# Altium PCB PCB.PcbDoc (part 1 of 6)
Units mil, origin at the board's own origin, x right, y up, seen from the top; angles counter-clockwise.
Board outline 7100 x 7000 mil, 4 copper layers (Top Layer, GND, VCC, Bottom Layer), stack 61.2 mil thick; 759 components, 507 nets, 2200 pads, 452 vias.
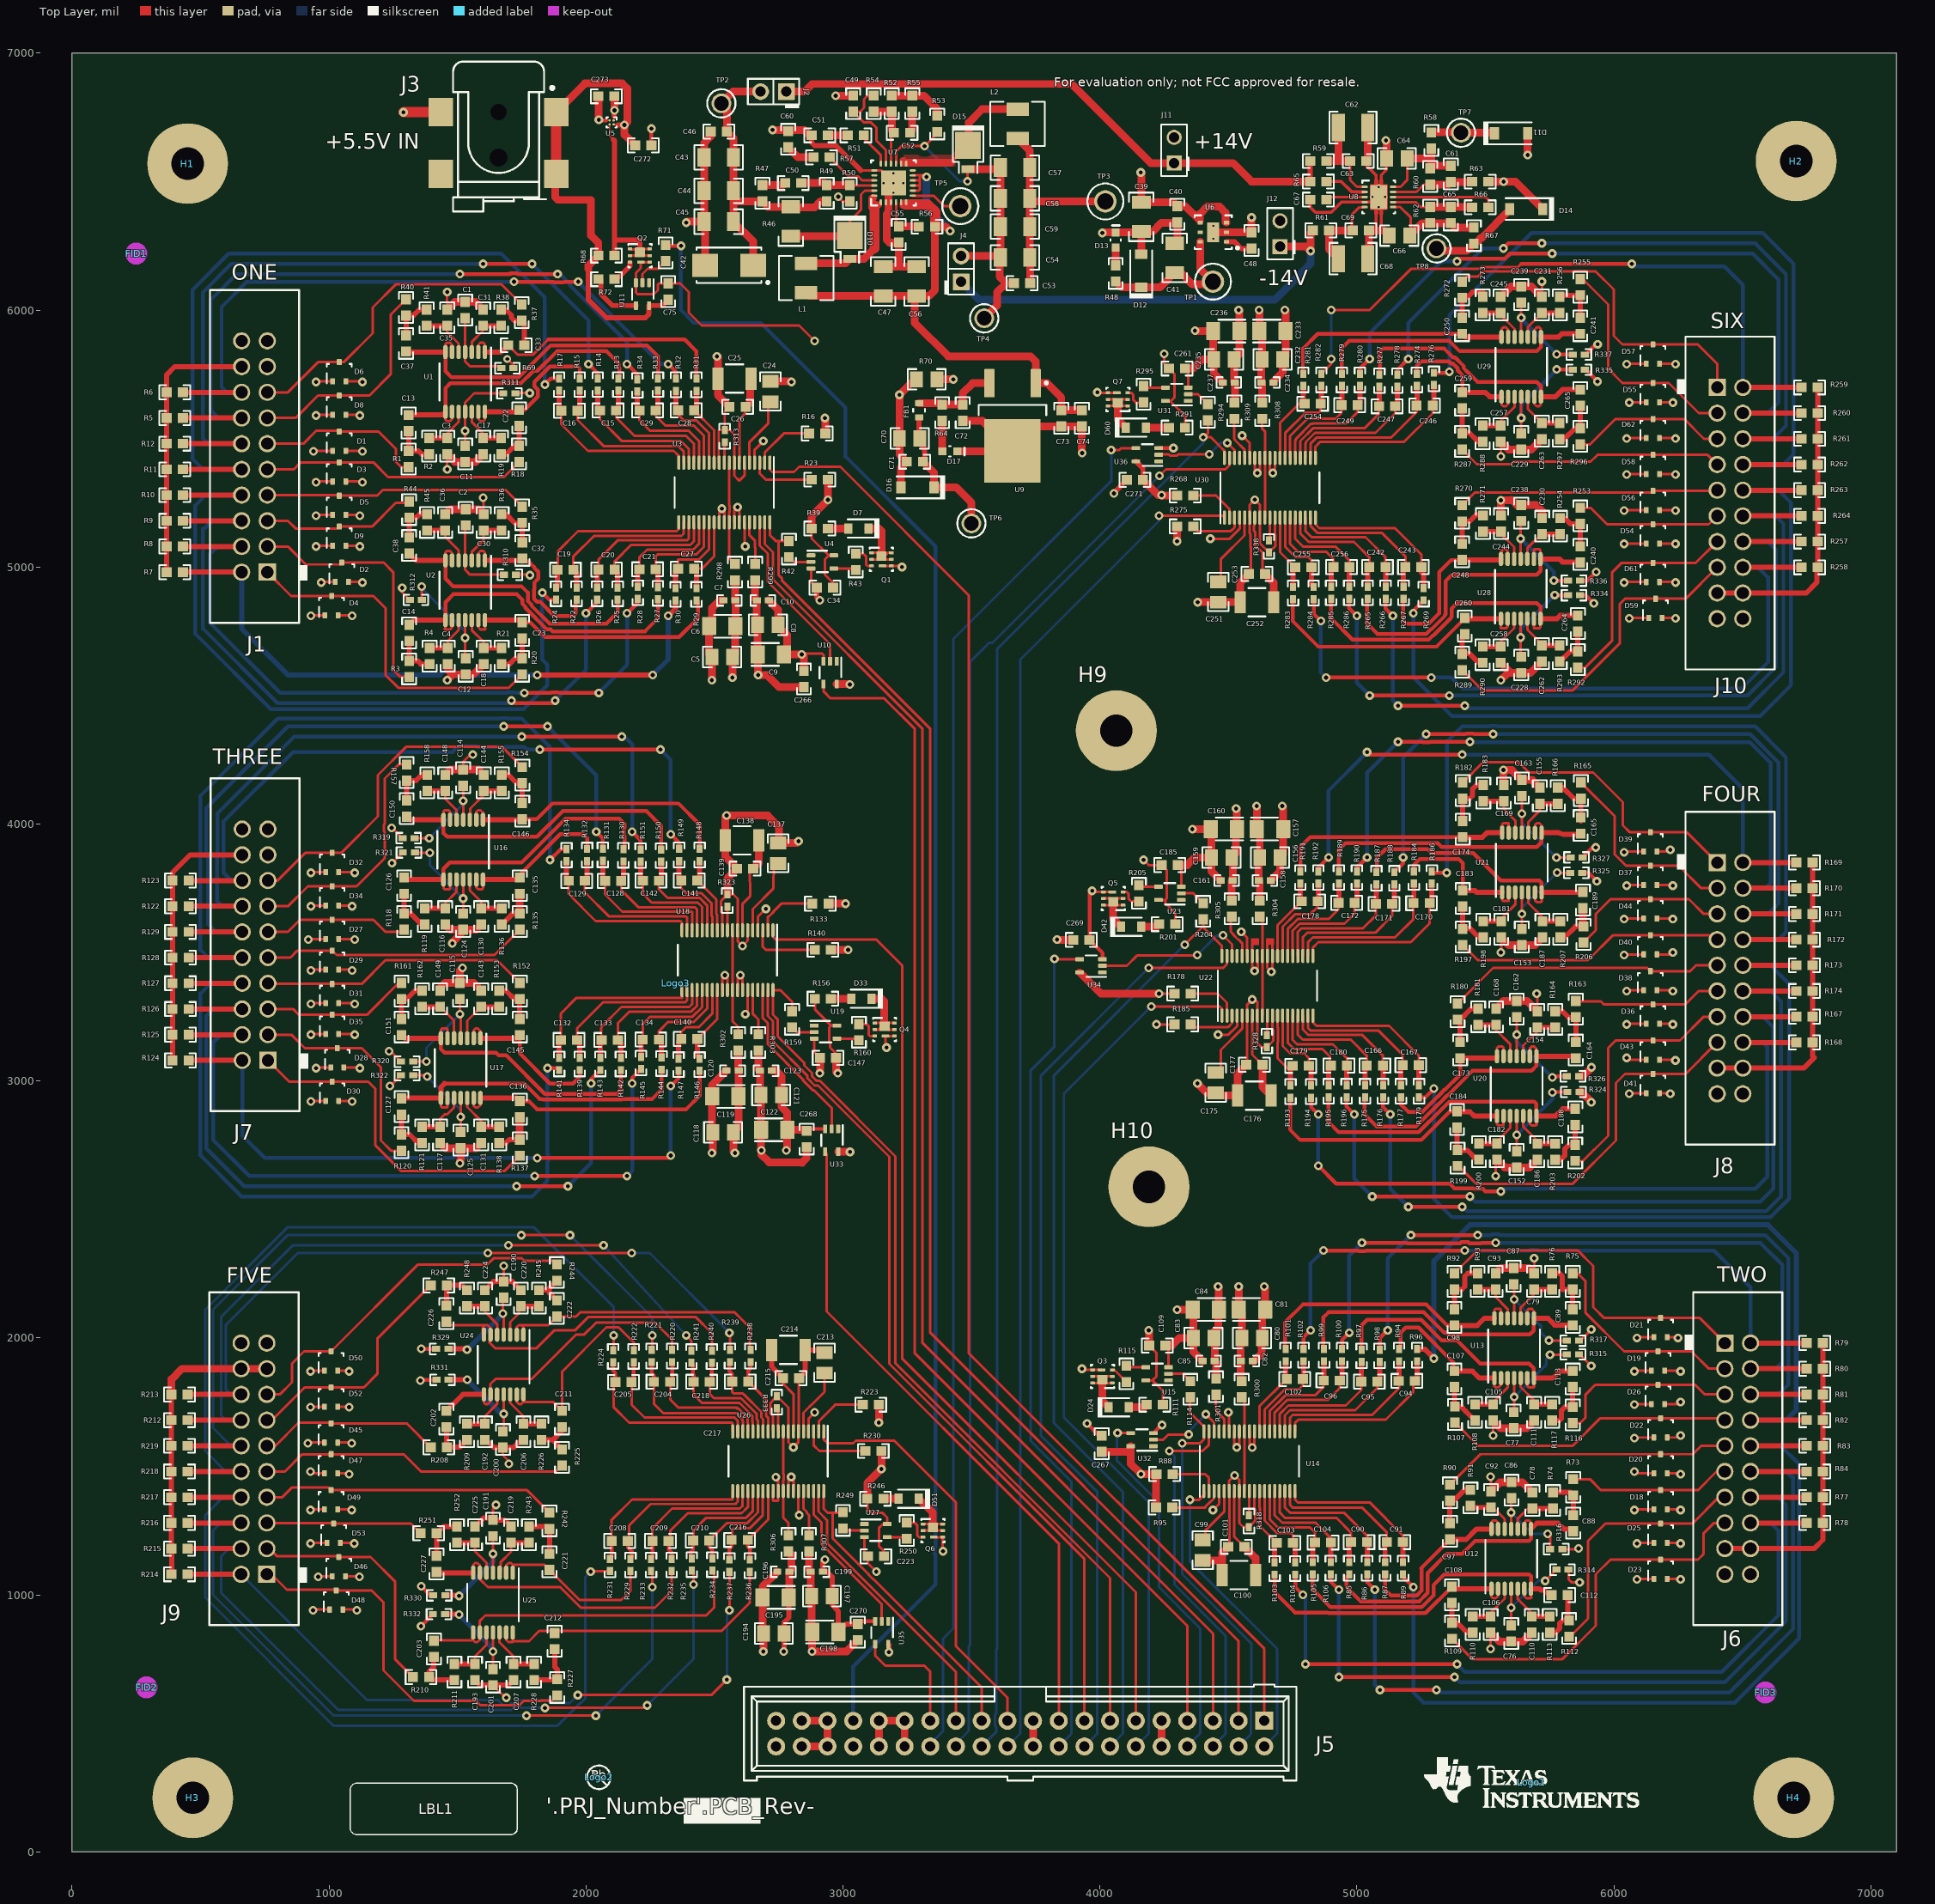
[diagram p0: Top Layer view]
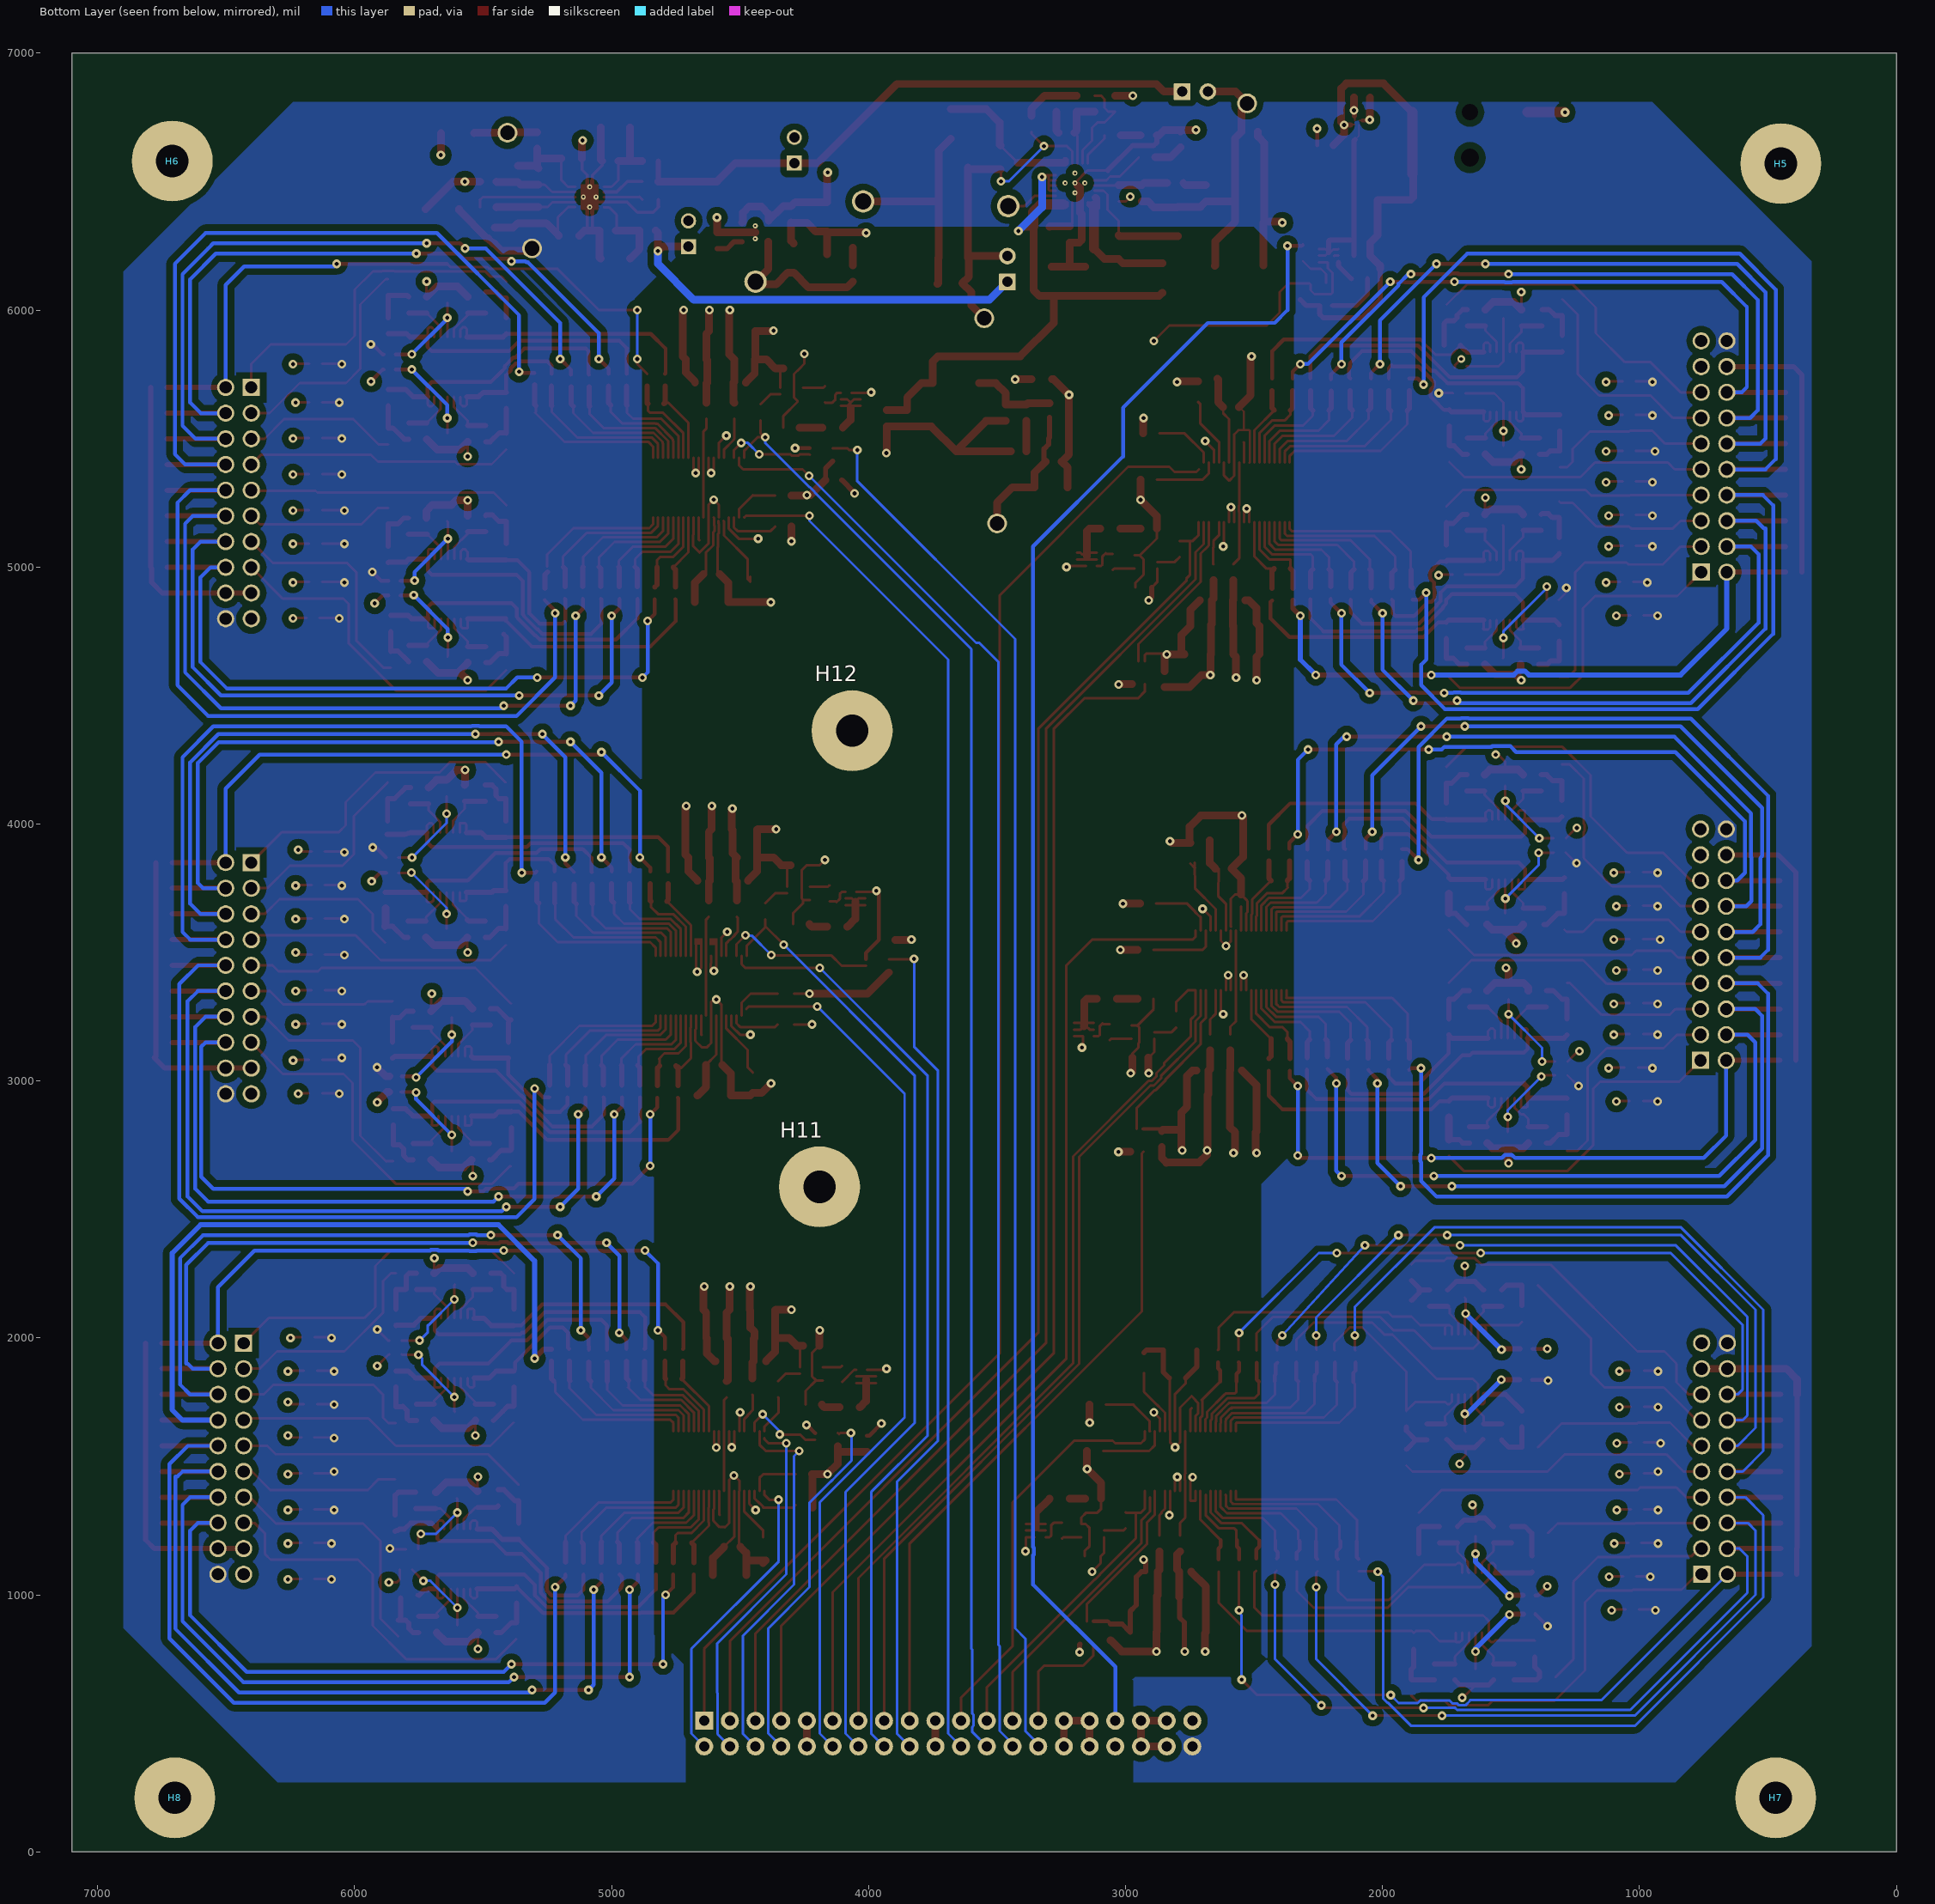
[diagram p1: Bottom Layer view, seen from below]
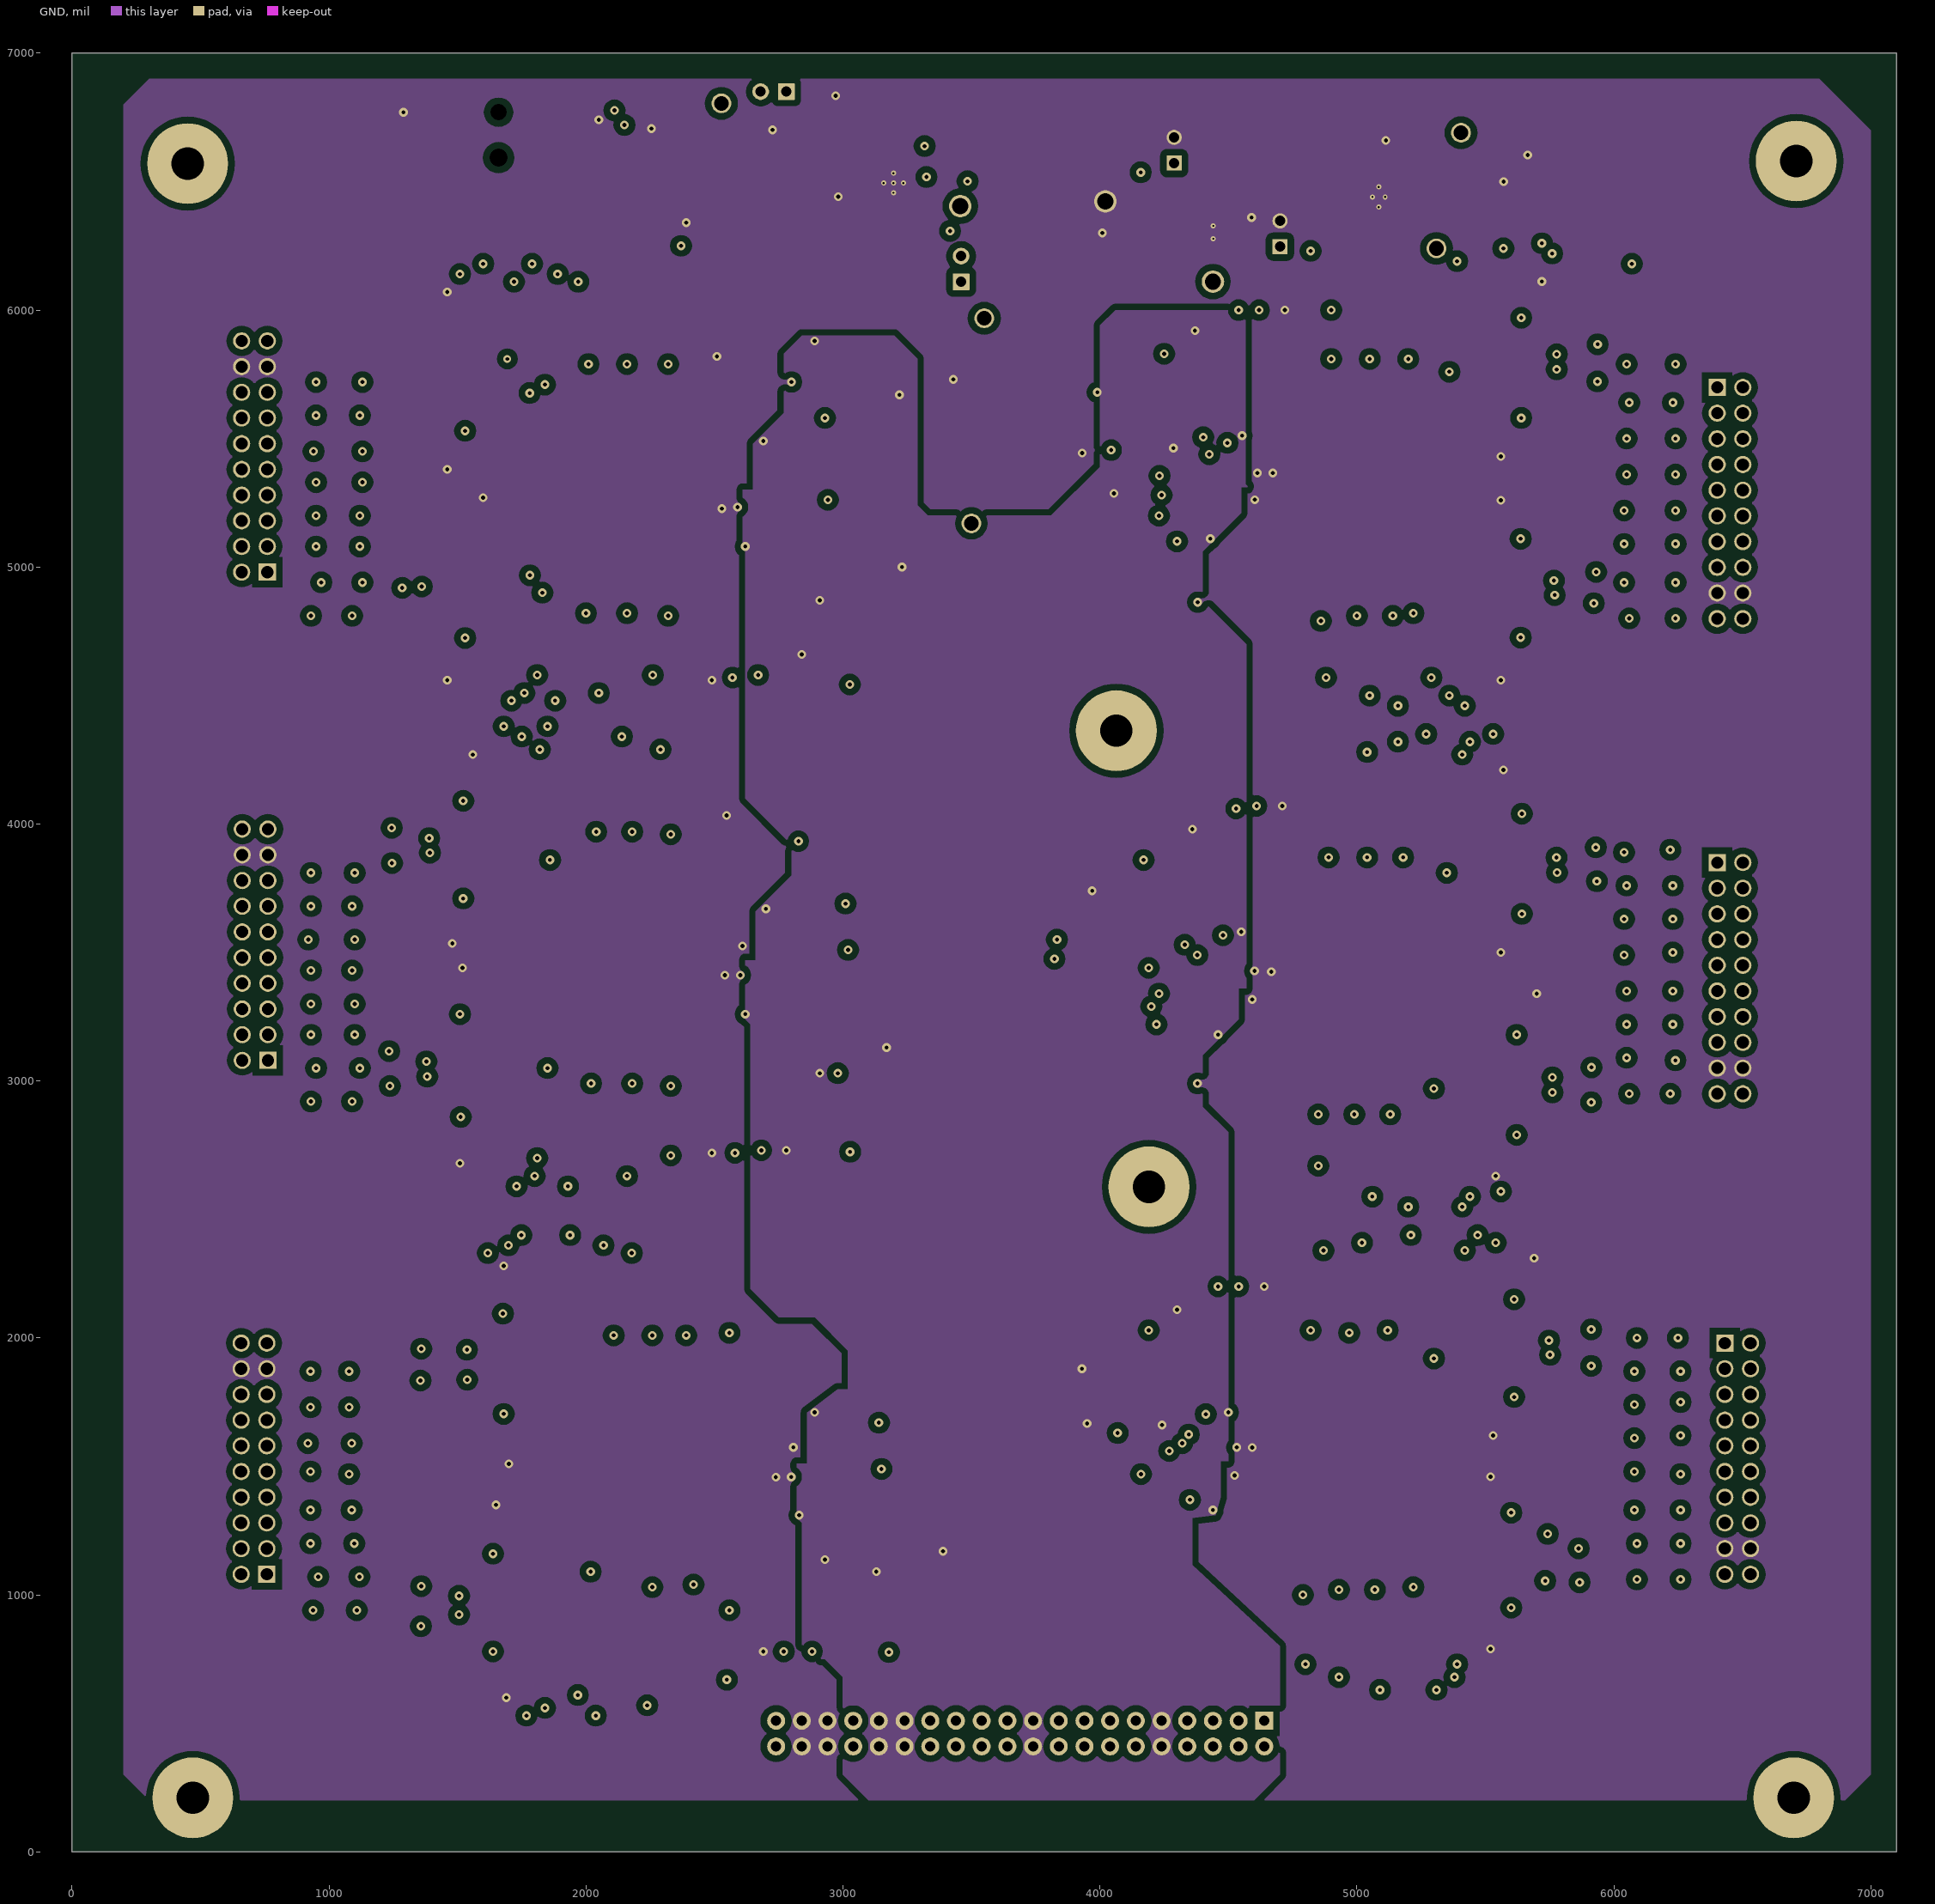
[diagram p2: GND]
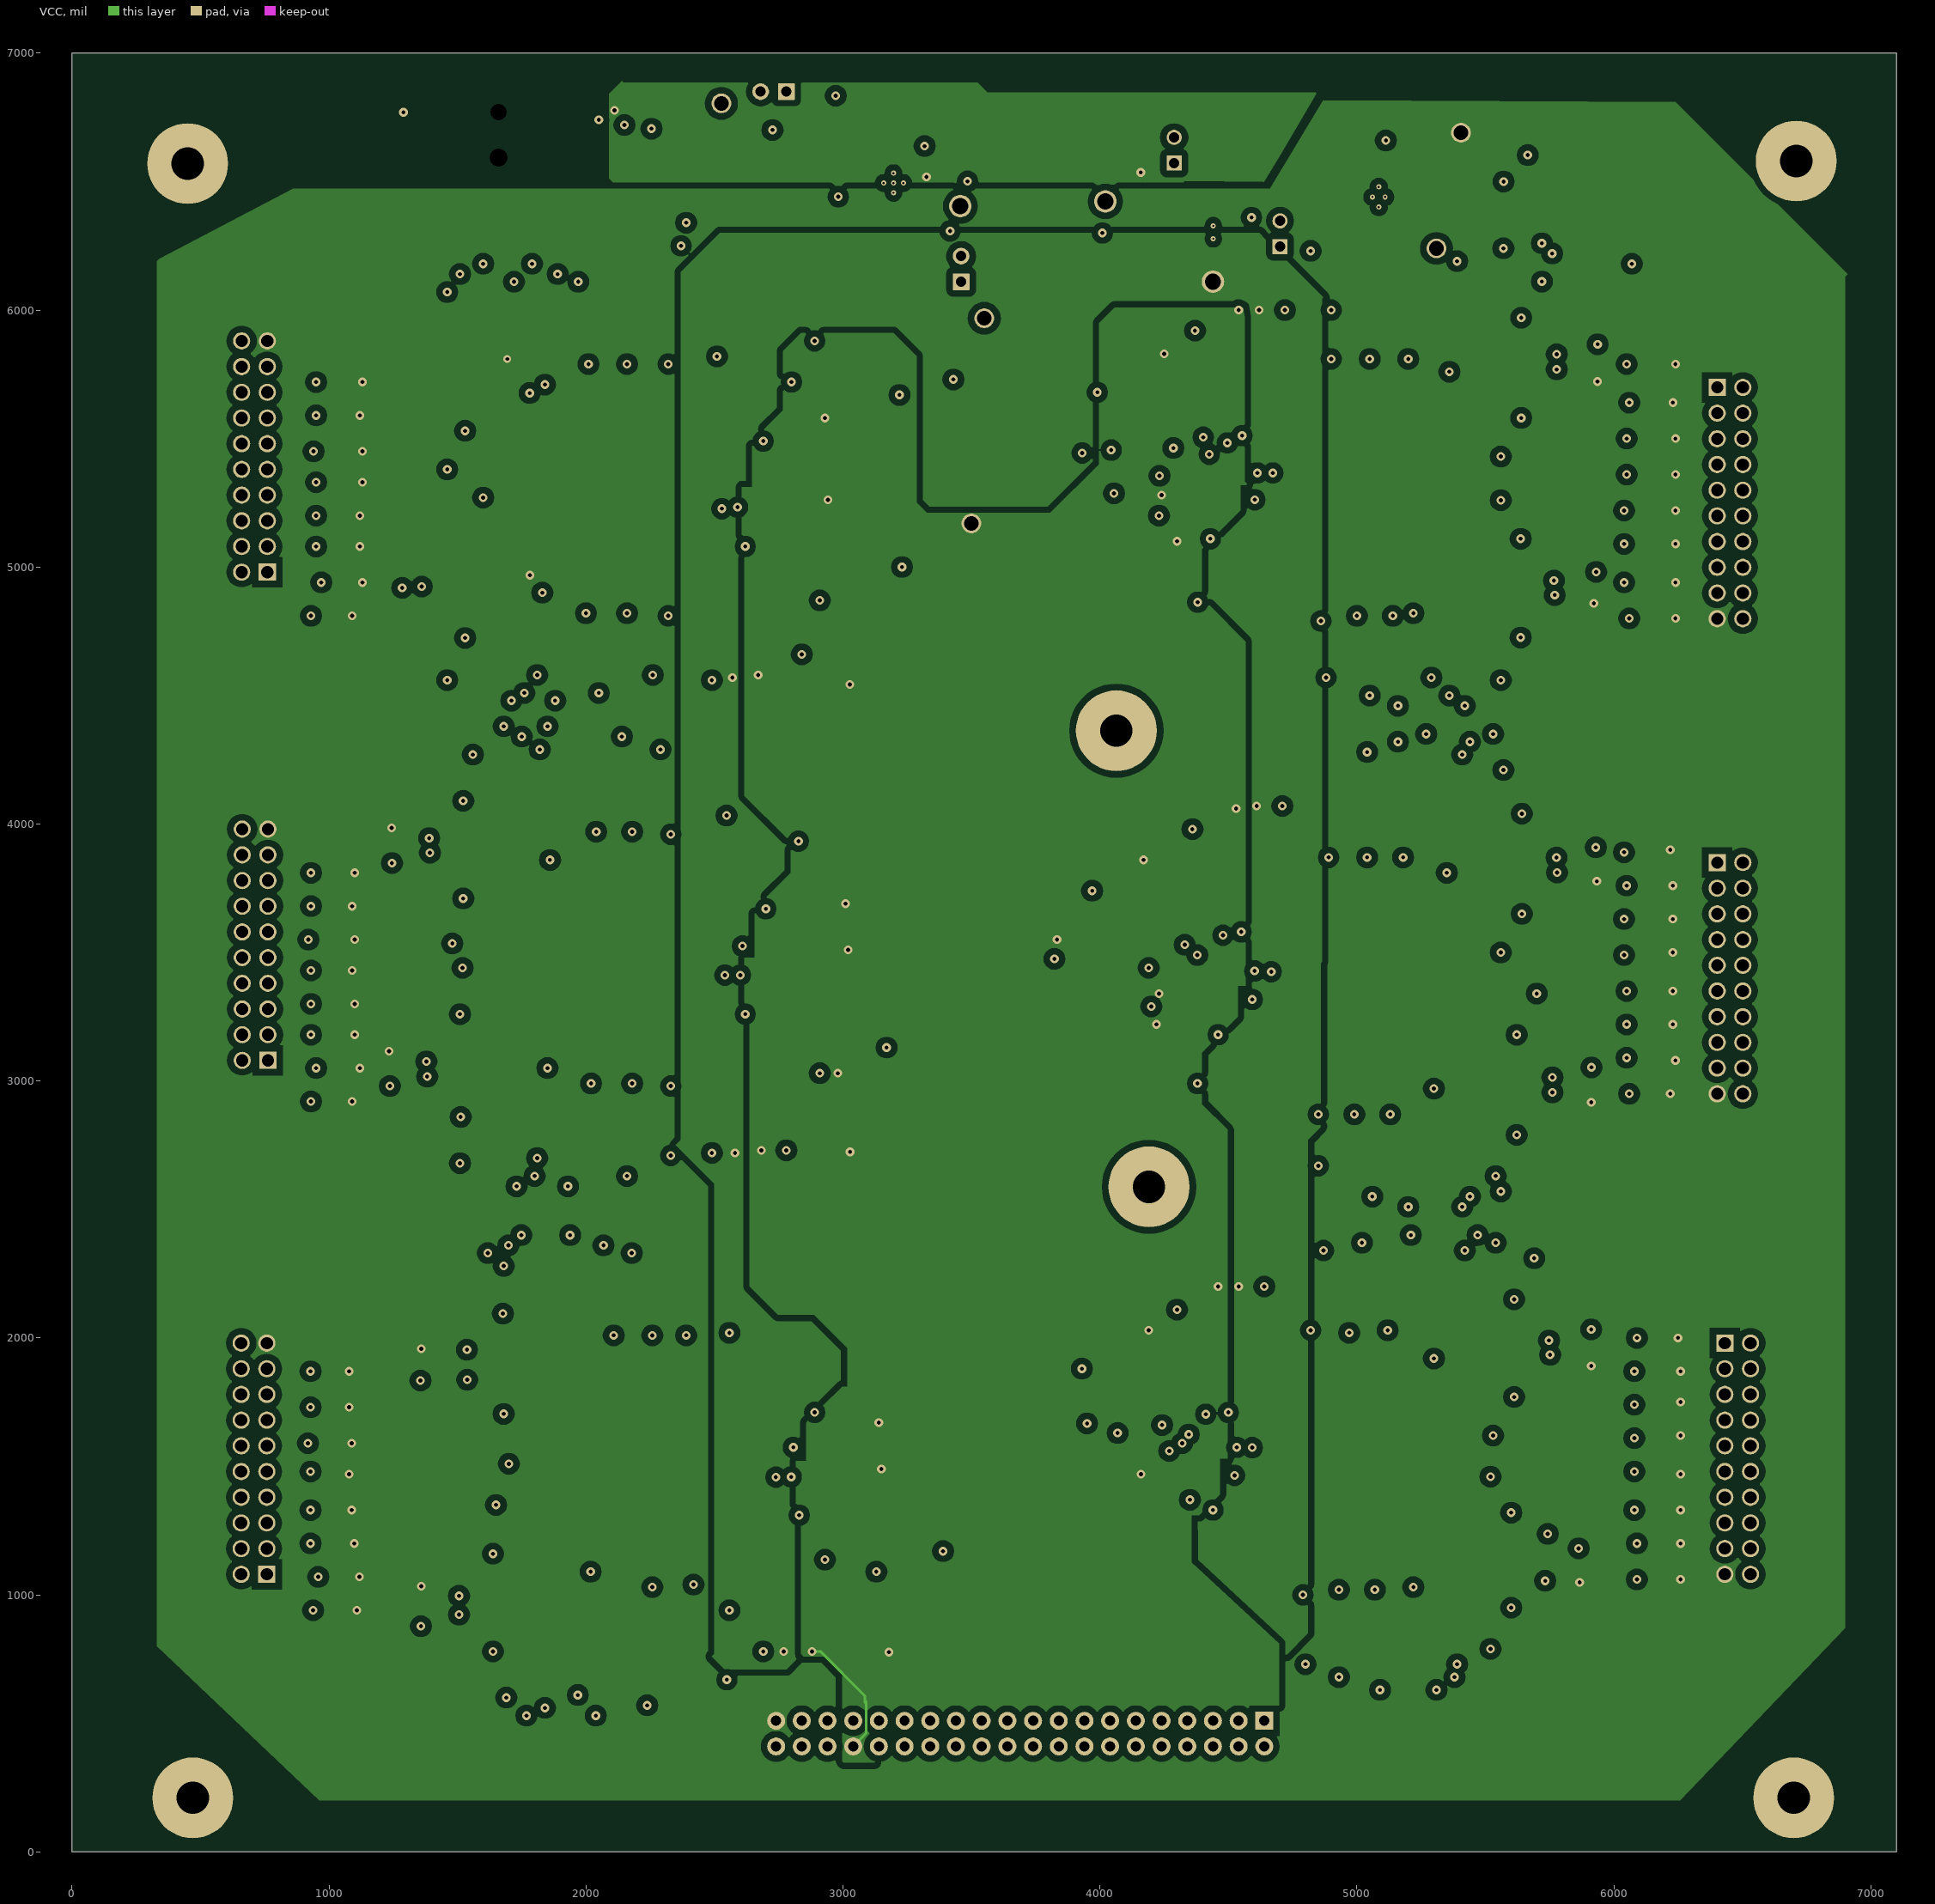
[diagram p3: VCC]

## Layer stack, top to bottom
Top Solder: solder mask 0.4, Solder Resist, Dk 3.5
Top Layer: signal copper 2.8
Dielectric1: core 16.6, FR-4, Dk 4.8
GND: signal copper 2.8
Dielectric 2: dielectric 16.8, FR-4, Dk 4.8
VCC: signal copper 2.8
Dielectric 3: dielectric 16.6, FR-4, Dk 4.8
Bottom Layer: signal copper 2.8
Bottom Solder: solder mask 0.4, Solder Resist, Dk 3.5

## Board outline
0,0 7100,0 7100,7000 0,7000 0,0

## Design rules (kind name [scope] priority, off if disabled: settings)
AcuteAngle [All] p1: minimum=4.50000000000000E+0001 checktracksonly=FALSE
AssemblyTestPointUsage [All] p1: valid=2
BoardOutlineClearance BoardOutlineClearance_MountingHoles [OnCopper and InComponentClass('Mounting Holes')] p1: gap=40
BoardOutlineClearance BoardOutlineClearance_Poly [OnCopper and IsPoly] p2: gap=25
BoardOutlineClearance [OnCopper and Not InComponentClass('Logo') and not InComponentClass('FiducialMark') and not InRegion(1000,500,4000,800) and not InPoly] p3: gap=75
Clearance Clearance_Keepouts [((IsTrack Or IsArc) And Not InPoly) And IsFree and IsKeepOut vs ((IsTrack Or IsArc) And Not InPoly) And IsFree and IsKeepOut] p1: gap=0
Clearance Clearance_Poly [InPolygon] p2: gap=25
Clearance [All] p3: gap=7.87
ComponentClearance ComponentClearance_MountingHoles_FiducialMarks [InComponentClass('Mounting Holes') vs InComponentClass('FiducialMark')] p1: gap=50 collisioncheckmode=3 verticalgap=10 showdistances=FALSE
ComponentClearance ComponentClearance_Shunt [InComponentClass('Header') vs InComponentClass('Shunt')] p2: gap=0 collisioncheckmode=3 verticalgap=0 showdistances=FALSE
ComponentClearance ComponentClearance_Logo [InComponentClass('Logo')] p3: gap=50 collisioncheckmode=3 verticalgap=10 showdistances=FALSE
ComponentClearance ComponentClearance_ScrewToNut [(HasFootprint('NY PMS 440 0025 PH')) vs (HasFootprint('Keystone_1902C'))] p4: gap=5 collisioncheckmode=3 verticalgap=10 showdistances=FALSE
ComponentClearance ComponentClearance_MountingHoles [InComponentClass('Mounting Holes')] p5: gap=250 collisioncheckmode=3 verticalgap=100000 showdistances=FALSE
ComponentClearance ComponentClearance_SmallPassives [HasFootprint('0201*') or HasFootprint('0402*') or HasFootprint('0508') or HasFootprint('0603*') or HasFootprint('0612') or HasFootprint('0805*') or HasFootprint('0815*') or HasFootprint('0830*') or HasFootprint('1206*') or HasFootprint('1210*') or HasFootprint('1808*') or HasFootprint('1812*') or HasFootprint('1825*') or HasFootprint('2010*') or HasFootprint('2220*') or HasFootprint('2225*') or HasFootprint('2512*') or HasFootprint('2728*') or HasFootprint('3518*') vs HasFootprint('0201*') or HasFootprint('0402*') or HasFootprint('0508') or HasFootprint('0603*') or HasFootprint('0612') or HasFootprint('0805*') or HasFootprint('0815*') or HasFootprint('0830*') or HasFootprint('1206*') or HasFootprint('1210*') or HasFootprint('1808*') or HasFootprint('1812*') or HasFootprint('1825*') or HasFootprint('2010*') or HasFootprint('2220*') or HasFootprint('2225*') or HasFootprint('2512*') or HasFootprint('2728*') or HasFootprint('3518*')] p6: gap=14.96 collisioncheckmode=3 verticalgap=10 showdistances=FALSE
ComponentClearance ComponentClearance_THtoSMT [IsThruComponent vs IsSMTComponent] p7: gap=40 collisioncheckmode=3 verticalgap=30 showdistances=FALSE
ComponentClearance ComponentClearance_THtoTH [IsThruComponent vs IsThruComponent] p8: gap=30 collisioncheckmode=3 verticalgap=30 showdistances=FALSE
ComponentClearance [All] p9: gap=30 collisioncheckmode=3 verticalgap=10 showdistances=FALSE
DiffPairsRouting [All] p1: maxlimit=100 minlimit=10 mostfreqgap=10 toplayer_minwidth=15 toplayer_maxwidth=15 toplayer_prefwidth=15 midlayer1_minwidth=15 midlayer1_maxwidth=15 midlayer1_prefwidth=15 midlayer2_minwidth=15 midlayer2_maxwidth=15 midlayer2_prefwidth=15 bottomlayer_minwidth=15 bottomlayer_maxwidth=15 bottomlayer_prefwidth=15 maxuncoupledlength=1000
FabricationTestPointUsage TestPointUsage [All] p1: valid=2 allowmultiple=FALSE
FabricationTestpoint Testpoint [All] p1: side=3 testpointundercomponent=TRUE minsize=40 maxsize=100 preferedsize=60 minholesize=0 maxholesize=40 preferedholesize=32 testpointgrid=1 allowsidetop=TRUE allowsidebottom=TRUE usegrid=TRUE gridtolerance=0.01
FanoutControl Fanout_LCC [IsLCC] p1: bgadir=Out bgaviamode=Centered fanoutstyle=Auto fanoutdirection=Alternating viagrid=1 // Fanout_LCC (Default Rule)
FanoutControl Fanout_BGA [IsBGA] p2: bgadir=Out bgaviamode=Centered fanoutstyle=Auto fanoutdirection=Alternating viagrid=1 // Fanout_BGA (Default Rule)
FanoutControl Fanout_Default [All] p4: bgadir=Out bgaviamode=Centered fanoutstyle=Auto fanoutdirection=Alternating viagrid=1 // Fanout_Default (Default Rule)
FanoutControl Fanout_Small [(CompPinCount < 5)] p5: bgadir=Out bgaviamode=Centered fanoutstyle=Auto fanoutdirection=OutThenIn viagrid=1 // Fanout_Small (Default Rule)
HoleSize [All] p1: absolutevalues=TRUE maxlimit=251 minlimit=7.87 maxpercent=80.000 minpercent=20.000
MinimumAnnularRing MinimumAnnularRing_ThermalPadVias [IsVia and InAnyComponent] p1: minimumring=5.91
MinimumAnnularRing [All] p2: minimumring=8
MinimumSolderMaskSliver MinimumSolderMaskSliver_Logo [InComponentClass('Logo') vs InComponentClass('Logo')] p1: minsoldermaskwidth=0.7
MinimumSolderMaskSliver [All] p2: minsoldermaskwidth=3.94
PlaneConnect [All] p1: planeconnectstyle=Relief reliefexpansion=10 reliefentries=4 reliefconductorwidth=10 reliefairgap=10
PolygonConnect [All] p1: connectstyle=Direct reliefconductorwidth=10 reliefentries=4 polygonreliefangle="90 Angle" airgapwidth=10
RoutingVias ThermalPadVias [IsVia and InAnyComponent] p1: holewidth=7.87 width=19.68 viastyle="Through Hole" minholewidth=7.87 minwidth=19.68 maxholewidth=12.99 maxwidth=23.62
RoutingVias [All] p2: holewidth=16 width=34 viastyle="Through Hole" minholewidth=7.87 minwidth=26 maxholewidth=40 maxwidth=65
SilkToBoardRegionClearance [Not ((IsComment or IsDesignator) And (Hide <> 'False')) and not InRegion(1000,500,4000,800)] p1:
SilkToSilkClearance SilkToSilkClearance_Pb-FreeLogo [(HasFootprint('Pb-Free_Overlay_Medium') OR HasFootprint('Pb-Free_Overlay_Small')) vs (HasFootprint('Pb-Free_Overlay_Medium') OR HasFootprint('Pb-Free_Overlay_Small'))] p1: silktosilkclearance=0
SilkToSilkClearance [All] p2: silktosilkclearance=4
SilkToSolderMaskClearance SilkToComponentPadClearance [(IsPad or IsFill or IsRegion) and InAnycomponent] p1: minsilkscreentomaskgap=5 clearancetoexposedcopper=TRUE
SilkToSolderMaskClearance "Silk to Solder Mask Opening" [All] p2: minsilkscreentomaskgap=4 clearancetoexposedcopper=FALSE
SolderMaskExpansion [All] p1: expansion=1.97
Width [All] p1: maxlimit=100 minlimit=6 preferedwidth=10 checkconnectedcopper=TRUE
15 further rules are at their usual default settings.

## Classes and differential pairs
component class Label: LBL1
component class AssemblyNote: ZZ1
component class FiducialMark: FID1 FID2 FID3
component class EVM_Hardware: FID1 FID2 FID3 H1 H2 H3 H4 H5 H6 H7 H8 H9 H10 H11 H12 LBL1 Logo1 Logo2 Logo3 ZZ1
component class Logo: Logo1
component class "Mounting Holes": H1 H2 H3 H4 H9 H10
component class Header: J2 J4 J11 J12
component class Page1: C1 C2 C3 C4 C5 C6 C7 C8 C9 C10 C11 C12 C13 C14 C15 C16 C17 C18 C19 C20 C21 C22 C23 C24 C25 C26 C27 C28 C29 C30 C31 C32 C33 C34 C35 C36 C37 C38 C266 D1 D2 D3 D4 D5 D6 D7 D8 D9 J1 Q1 R1 R2 R3 R4 R5 R6 R7 R8 R9 R10 R11 R12 R13 R14 R15 R16 R17 R18 R19 R20 R21 R22 R23 R24 R25 R26 R27 R28 R29 R30 R31 R32 R33 R34 R35 R36 R37 R38 R39 R40 R41 R42 R43 R44 R45 R69 R298 R299 R310 R311 R312 R313 U1 U2 U3 U4 U10
component class Page2: C76 C77 C78 C79 C80 C81 C82 C83 C84 C85 C86 C87 C88 C89 C90 C91 C92 C93 C94 C95 C96 C97 C98 C99 C100 C101 C102 C103 C104 C105 C106 C107 C108 C109 C110 C111 C112 C113 C267 D18 D19 D20 D21 D22 D23 D24 D25 D26 J6 Q3 R73 R74 R75 R76 R77 R78 R79 R80 R81 R82 R83 R84 R85 R86 R87 R88 R89 R90 R91 R92 R93 R94 R95 R96 R97 R98 R99 R100 R101 R102 R103 R104 R105 R106 R107 R108 R109 R110 R111 R112 R113 R114 R115 R116 R117 R300 R301 R314 R315 R316 R317 R318 U12 U13 U14 U15 U32
component class Page3: C114 C115 C116 C117 C118 C119 C120 C121 C122 C123 C124 C125 C126 C127 C128 C129 C130 C131 C132 C133 C134 C135 C136 C137 C138 C139 C140 C141 C142 C143 C144 C145 C146 C147 C148 C149 C150 C151 C268 D27 D28 D29 D30 D31 D32 D33 D34 D35 J7 Q4 R118 R119 R120 R121 R122 R123 R124 R125 R126 R127 R128 R129 R130 R131 R132 R133 R134 R135 R136 R137 R138 R139 R140 R141 R142 R143 R144 R145 R146 R147 R148 R149 R150 R151 R152 R153 R154 R155 R156 R157 R158 R159 R160 R161 R162 R302 R303 R319 R320 R321 R322 R323 U16 U17 U18 U19 U33
component class Page4: C152 C153 C154 C155 C156 C157 C158 C159 C160 C161 C162 C163 C164 C165 C166 C167 C168 C169 C170 C171 C172 C173 C174 C175 C176 C177 C178 C179 C180 C181 C182 C183 C184 C185 C186 C187 C188 C189 C269 D36 D37 D38 D39 D40 D41 D42 D43 D44 J8 Q5 R163 R164 R165 R166 R167 R168 R169 R170 R171 R172 R173 R174 R175 R176 R177 R178 R179 R180 R181 R182 R183 R184 R185 R186 R187 R188 R189 R190 R191 R192 R193 R194 R195 R196 R197 R198 R199 R200 R201 R202 R203 R204 R205 R206 R207 R304 R305 R324 R325 R326 R327 R328 U20 U21 U22 U23 U34
component class Page5: C190 C191 C192 C193 C194 C195 C196 C197 C198 C199 C200 C201 C202 C203 C204 C205 C206 C207 C208 C209 C210 C211 C212 C213 C214 C215 C216 C217 C218 C219 C220 C221 C222 C223 C224 C225 C226 C227 C270 D45 D46 D47 D48 D49 D50 D51 D52 D53 J9 Q6 R208 R209 R210 R211 R212 R213 R214 R215 R216 R217 R218 R219 R220 R221 R222 R223 R224 R225 R226 R227 R228 R229 R230 R231 R232 R233 R234 R235 R236 R237 R238 R239 R240 R241 R242 R243 R244 R245 R246 R247 R248 R249 R250 R251 R252 R306 R307 R329 R330 R331 R332 R333 U24 U25 U26 U27 U35
component class Page6: C228 C229 C230 C231 C232 C233 C234 C235 C236 C237 C238 C239 C240 C241 C242 C243 C244 C245 C246 C247 C248 C249 C250 C251 C252 C253 C254 C255 C256 C257 C258 C259 C260 C261 C262 C263 C264 C265 C271 D54 D55 D56 D57 D58 D59 D60 D61 D62 J10 Q7 R253 R254 R255 R256 R257 R258 R259 R260 R261 R262 R263 R264 R265 R266 R267 R268 R269 R270 R271 R272 R273 R274 R275 R276 R277 R278 R279 R280 R281 R282 R283 R284 R285 R286 R287 R288 R289 R290 R291 R292 R293 R294 R295 R296 R297 R308 R309 R334 R335 R336 R337 R338 U28 U29 U30 U31 U36
component class Paget2: C39 C40 C41 C42 C43 C44 C45 C46 C47 C48 C49 C50 C51 C52 C53 C54 C55 C56 C57 C58 C59 C60 C61 C62 C63 C64 C65 C66 C67 C68 C69 C70 C71 C72 C73 C74 C75 C272 C273 D10 D11 D12 D13 D14 D15 D16 D17 FB1 J2 J3 J4 J5 J11 J12 L1 L2 Q2 R46 R47 R48 R49 R50 R51 R52 R53 R54 R55 R56 R57 R58 R59 R60 R61 R62 R63 R64 R65 R66 R67 R68 R70 R71 R72 SH-J1 SH-J2 TP1 TP2 TP3 TP4 TP5 TP6 TP7 TP8 U5 U6 U7 U8 U9 U11

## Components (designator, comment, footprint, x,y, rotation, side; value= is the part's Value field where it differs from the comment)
C1 "06035C104KAT2A" 0603 1530,6000.31 r270 top
C2 "06035C104KAT2A" 0603 1532,5193.69 r270 top
C3 "C0603C470J5GACTU" 0603 1460,5470.31 r90 top
C4 "C0603C470J5GACTU" 0603 1462,4653.69 r90 top
C5 "LMK212B7105KD-T" 0805_HV 2530,4650 r180 top
C6 "TAJA106M010RNJ" 3216-18 2530,4770 r180 top
C7 "C1005X5R1A104K050BA" 0402 2558.26,4870 r180 top
C8 "LMK212B7105KD-T" 0805_HV 2708.26,4775.38 r0 top
C9 "TAJA106M010RNJ" 3216-18 2720,4660 r0 top
C10 "C1005X5R1A104K050BA" 0402 2688.26,4870 r0 top
C11 "06035C104KAT2A" 0603 1530,5440.31 r90 top
C12 "06035C104KAT2A" 0603 1532,4613.69 r90 top
C13 "06035A101FAT2A" 0603 1310,5560.31 r270 top
C14 "06035A101FAT2A" 0603 1312,4743.69 r270 top
C15 "C1608X7R1H103K080AA" 0603 2085.76,5609.44 r180 top
C16 "C1608X7R1H103K080AA" 0603 1935.78,5608.12 r180 top
C17 "C0603C470J5GACTU" 0603 1600,5470.31 r90 top
C18 "C0603C470J5GACTU" 0603 1602,4653.69 r90 top
C19 "C1608X7R1H103K080AA" 0603 1920,4989.59 r180 top
C20 "C1608X7R1H103K080AA" 0603 2080.25,4990 r180 top
C21 "C1608X7R1H103K080AA" 0603 2240,4991.22 r180 top
C22 "06035A101FAT2A" 0603 1740,5580.31 r270 top
C23 "06035A101FAT2A" 0603 1752,4753.69 r270 top
C24 "GRM21BR71A106KE51L" 0805_HV 2718.26,5683.26 r90 top
C25 "C3225X7R1C226K250AC" 1210_280 2578.26,5733.26 r180 top
C26 "C1608X7R1C105K080AC" 0603 2590,5623.26 r180 top
C27 "C1608X7R1H103K080AA" 0603 2390,4993.57 r180 top
C28 "C1608X7R1H103K080AA" 0603 2390,5609.95 r180 top
C29 "C1608X7R1H103K080AA" 0603 2240.21,5609.44 r180 top
C30 "C0603C470J5GACTU" 0603 1602,5173.69 r270 top
C31 "C0603C470J5GACTU" 0603 1600,5970.31 r270 top
C32 "06035A101FAT2A" 0603 1753,5065 r90 top
C33 "06035A101FAT2A" 0603 1729,5863 r0 top
C34 "GRM188R71C104KA01D" 0603 2930,4920 r180 top
C35 "C0603C470J5GACTU" 0603 1460,5970.31 r270 top
C36 "C0603C470J5GACTU" 0603 1452,5173.69 r270 top
C37 "06035A101FAT2A" 0603 1300,5870.31 r90 top
C38 "06035A101FAT2A" 0603 1312,5083.69 r90 top
C39 "885012208069" 1206 4161.32,6362.76 r270 top
C40 "06033C104JAT2A" 0603 4301.32,6372.76 r270 top
C41 "C3216X7R1E475M160AC" 1206 4291.32,6202.76 r90 top
C42 "293D475X9025C2TE3" 6032-28 2556.93,6174.25 r180 top
C43 "C3216X7R1E475M160AC" 1206 2516.93,6594.25 r180 top
C44 "C3216X7R1E475M160AC" 1206 2516.93,6464.25 r180 top
C45 "C3216X7R1E475M160AC" 1206 2516.93,6344.25 r180 top
C46 "GRM188R70J103KA01D" 0603 2516.93,6694.25 r180 top
C47 "C3216X7R1E475M160AC" 1206 3156.93,6111.66 r90 top
C48 "C1608X7R1H103K080AA" 0603 4590,6270.81 r90 top
C49 "C0603C224K9RACTU" 0603 3040,6803.27 r270 top
C50 "C0603C100J5GACTU" 0603 2806.93,6494.57 r0 top
C51 "GRM188R70J103KA01D" 0603 2910,6680 r0 top
C52 "C0603C100J5GACTU" 0603 3230,6690 r180 top
C53 "06033C104JAT2A" 0603 3696.93,6104.57 r0 top
C54 "C3216X7R1E475M160AC" 1206 3670,6204.57 r0 top
C55 "GRM188R61E105KA12D" 0603 3216.93,6294.57 r270 top
C56 "C3216X7R1E475M160AC" 1206 3286.93,6111.66 r90 top
C57 "C3216X7R1E475M160AC" 1206 3670,6554.57 r0 top
C58 "C3216X7R1E475M160AC" 1206 3670,6434.57 r0 top
C59 "C3216X7R1E475M160AC" 1206 3670,6324.57 r0 top
C60 "GRM188R70J103KA01D" 0603 2786.93,6664.57 r90 top
C61 "06033C104JAT2A" 0603 5365.39,6530 r270 top
C62 "" 1210 4985.39,6710 r180 top
C63 "GRM188R61E105KA12D" 0603 5005.39,6580 r0 top
C64 "C0805C225K8RACTU" 0805_HV 5155.39,6590 r180 top
C65 "06033C104JAT2A" 0603 5365.39,6370 r90 top
C66 "C0805C225K8RACTU" 0805_HV 5165.39,6290 r180 top
C67 "GRM188R70J103KA01D" 0603 4850,6430 r180 top
C68 "" 1210 4985.39,6200 r180 top
C69 "GRM188R61E105KA12D" 0603 5015.39,6310 r0 top
C70 "C2012X5R1H475M125AB" 0805_HV 3260,5500 r180 top
C71 "C0603C104K5RACTU" 0603 3280,5410 r180 top
C72 "CGA3E3X5R1H105K080AB" 0603 3466.18,5600.39 r270 top
C73 "CGA3E3X5R1H105K080AB" 0603 3850,5578.7 r270 top
C74 "C0603C104K5RACTU" 0603 3930,5578.7 r270 top
C75 "GRM188R71C104KA01D" 0603 2320,6071.97 r90 top
C76 "06035C104KAT2A" 0603 5600.73,850 r90 top
C77 "06035C104KAT2A" 0603 5610,1680 r90 top
C78 "C0603C470J5GACTU" 0603 5683.35,1367.24 r270 top
C79 "C0603C470J5GACTU" 0603 5690,2220 r270 top
C80 "LMK212B7105KD-T" 0805_HV 4592.05,2000 r0 top
C81 "TAJA106M010RNJ" 3216-18 4592.05,2110 r0 top
C82 "C1005X5R1A104K050BA" 0402 4572.05,1910 r0 top
C83 "LMK212B7105KD-T" 0805_HV 4403.35,2000 r180 top
C84 "TAJA106M010RNJ" 3216-18 4412.05,2110 r180 top
C85 "C1005X5R1A104K050BA" 0402 4423.35,1910 r180 top
C86 "06035C104KAT2A" 0603 5602.05,1407.24 r270 top
C87 "06035C104KAT2A" 0603 5610,2240 r270 top
C88 "06035A101FAT2A" 0603 5842.05,1278.74 r90 top
C89 "06035A101FAT2A" 0603 5840,2080 r90 top
C90 "C1608X7R1H103K080AA" 0603 5008.19,1205.28 r0 top
C91 "C1608X7R1H103K080AA" 0603 5148.19,1205.28 r0 top
C92 "C0603C470J5GACTU" 0603 5522.05,1371.69 r270 top
C93 "C0603C470J5GACTU" 0603 5540,2220 r270 top
C94 "C1608X7R1H103K080AA" 0603 5194.45,1832.8 r0 top
C95 "C1608X7R1H103K080AA" 0603 5048.5,1830 r0 top
C96 "C1608X7R1H103K080AA" 0603 4902.5,1834.3 r0 top
C97 "06035A101FAT2A" 0603 5362.05,1247.24 r90 top
C98 "06035A101FAT2A" 0603 5380,2080 r90 top
C99 "GRM21BR71A106KE51L" 0805_HV 4400,1174 r270 top
C100 "C3225X7R1C226K250AC" 1210_280 4541,1077 r180 top
C101 "C1608X7R1C105K080AC" 0603 4531,1187 r180 top
C102 "C1608X7R1H103K080AA" 0603 4758.5,1840 r0 top
C103 "C1608X7R1H103K080AA" 0603 4720,1202.32 r0 top
C104 "C1608X7R1H103K080AA" 0603 4868.21,1203.62 r0 top
C105 "C0603C470J5GACTU" 0603 5530,1710 r90 top
C106 "C0603C470J5GACTU" 0603 5520.73,884.45 r90 top
C107 "06035A101FAT2A" 0603 5380,1840 r270 top
C108 "06035A101FAT2A" 0603 5370,1000 r270 top
C109 "GRM188R71C104KA01D" 0603 4223.35,1970 r0 top
C110 "C0603C470J5GACTU" 0603 5680.73,884.45 r90 top
C111 "C0603C470J5GACTU" 0603 5690,1710 r90 top
C112 "06035A101FAT2A" 0603 5789,999 r0 top
C113 "06035A101FAT2A" 0603 5840,1840 r270 top
C114 "06035C104KAT2A" 0603 1522.36,4180 r270 top
C115 "06035C104KAT2A" 0603 1510,3350 r270 top
C116 "C0603C470J5GACTU" 0603 1452.36,3640 r90 top
C117 "C0603C470J5GACTU" 0603 1432.36,2790 r90 top
C118 "LMK212B7105KD-T" 0805_HV 2533.69,2799.95 r180 top
C119 "TAJA106M010RNJ" 3216-18 2542.36,2940 r180 top
C120 "C1005X5R1A104K050BA" 0402 2570.62,3040 r180 top
C121 "LMK212B7105KD-T" 0805_HV 2720.62,2945.38 r0 top
C122 "TAJA106M010RNJ" 3216-18 2732.36,2810 r0 top
C123 "C1005X5R1A104K050BA" 0402 2700.62,3040 r0 top
C124 "06035C104KAT2A" 0603 1522.36,3620 r90 top
C125 "06035C104KAT2A" 0603 1512.36,2770 r90 top
C126 "06035A101FAT2A" 0603 1292.36,3760 r270 top
C127 "06035A101FAT2A" 0603 1282.36,2900 r270 top
C128 "C1608X7R1H103K080AA" 0603 2105.55,3778.12 r180 top
C129 "C1608X7R1H103K080AA" 0603 1964.45,3778.7 r180 top
C130 "C0603C470J5GACTU" 0603 1592.36,3640 r90 top
C131 "C0603C470J5GACTU" 0603 1592.36,2790 r90 top
C132 "C1608X7R1H103K080AA" 0603 1933.91,3159.59 r180 top
C133 "C1608X7R1H103K080AA" 0603 2092.61,3159.59 r180 top
C134 "C1608X7R1H103K080AA" 0603 2252.36,3161.22 r180 top
C135 "06035A101FAT2A" 0603 1742.36,3760 r270 top
C136 "06035A101FAT2A" 0603 1742.36,2890 r270 top
C137 "GRM21BR71A106KE51L" 0805_HV 2747.62,3886.26 r90 top
C138 "C3225X7R1C226K250AC" 1210_280 2607.62,3936.26 r180 top
C139 "C1608X7R1C105K080AC" 0603 2619.36,3826.26 r180 top
C140 "C1608X7R1H103K080AA" 0603 2402.36,3163.57 r180 top
C141 "C1608X7R1H103K080AA" 0603 2402.36,3779.95 r180 top
C142 "C1608X7R1H103K080AA" 0603 2252.57,3779.44 r180 top
C143 "C0603C470J5GACTU" 0603 1592.36,3320 r270 top
C144 "C0603C470J5GACTU" 0603 1602.36,4160 r270 top
C145 "06035A101FAT2A" 0603 1742.36,3210 r90 top
C146 "06035A101FAT2A" 0603 1752.36,4050 r90 top
C147 "GRM188R71C104KA01D" 0603 2942.36,3090 r180 top
C148 "C0603C470J5GACTU" 0603 1452.36,4160 r270 top
C149 "C0603C470J5GACTU" 0603 1432.36,3320 r270 top
C150 "06035A101FAT2A" 0603 1302.36,4060 r90 top
C151 "06035A101FAT2A" 0603 1282.36,3210 r90 top
C152 "06035C104KAT2A" 0603 5622.05,2694.45 r90 top
C153 "06035C104KAT2A" 0603 5642.05,3560 r90 top
C154 "C0603C470J5GACTU" 0603 5702.05,3240 r270 top
C155 "C0603C470J5GACTU" 0603 5712.05,4110 r270 top
C156 "LMK212B7105KD-T" 0805_HV 4662.05,3870 r0 top
C157 "TAJA106M010RNJ" 3216-18 4662.05,3980 r0 top
C158 "C1005X5R1A104K050BA" 0402 4642.05,3780 r0 top
C159 "LMK212B7105KD-T" 0805_HV 4473.35,3870 r180 top
C160 "TAJA106M010RNJ" 3216-18 4482.05,3980 r180 top
C161 "C1005X5R1A104K050BA" 0402 4493.35,3780 r180 top
C162 "06035C104KAT2A" 0603 5622.05,3280 r270 top
C163 "06035C104KAT2A" 0603 5642.05,4140 r270 top
C164 "06035A101FAT2A" 0603 5852.05,3120 r90 top
C165 "06035A101FAT2A" 0603 5871,3994 r90 top
C166 "C1608X7R1H103K080AA" 0603 5070,3060 r0 top
C167 "C1608X7R1H103K080AA" 0603 5210,3061.65 r0 top
C168 "C0603C470J5GACTU" 0603 5542.05,3250 r270 top
C169 "C0603C470J5GACTU" 0603 5572.05,4120 r270 top
C170 "C1608X7R1H103K080AA" 0603 5251.95,3691.81 r0 top
C171 "C1608X7R1H103K080AA" 0603 5106,3689.01 r0 top
C172 "C1608X7R1H103K080AA" 0603 4960,3693.31 r0 top
C173 "06035A101FAT2A" 0603 5402.05,3120 r90 top
C174 "06035A101FAT2A" 0603 5412.05,3980 r90 top
C175 "GRM21BR71A106KE51L" 0805_HV 4451,2993 r270 top
C176 "C3225X7R1C226K250AC" 1210_280 4601,2943 r180 top
C177 "C1608X7R1C105K080AC" 0603 4601,3063 r180 top
C178 "C1608X7R1H103K080AA" 0603 4816,3699.01 r0 top
C179 "C1608X7R1H103K080AA" 0603 4781.81,3058.7 r0 top
C180 "C1608X7R1H103K080AA" 0603 4930.02,3060 r0 top
C181 "C0603C470J5GACTU" 0603 5562.05,3590 r90 top
C182 "C0603C470J5GACTU" 0603 5545,2724.98 r90 top
C183 "06035A101FAT2A" 0603 5412.05,3710 r270 top
C184 "06035A101FAT2A" 0603 5390,2850 r270 top
C185 "GRM188R71C104KA01D" 0603 4272.05,3840 r0 top
C186 "C0603C470J5GACTU" 0603 5702.05,2724.45 r90 top
C187 "C0603C470J5GACTU" 0603 5722.05,3590 r90 top
C188 "06035A101FAT2A" 0603 5850,2860 r270 top
C189 "06035A101FAT2A" 0603 5880,3704 r270 top
C190 "06035C104KAT2A" 0603 1679.76,2187.93 r270 top
C191 "06035C104KAT2A" 0603 1638.26,1259.95 r270 top
C192 "C0603C470J5GACTU" 0603 1606.96,1634.4 r90 top
C193 "C0603C470J5GACTU" 0603 1568.26,699.95 r90 top
C194 "LMK212B7105KD-T" 0805_HV 2731.33,849.95 r180 top
C195 "TAJA106M010RNJ" 3216-18 2738.26,989.95 r180 top
C196 "C1005X5R1A104K050BA" 0402 2768.26,1089.95 r180 top
C197 "LMK212B7105KD-T" 0805_HV 2918.26,995.38 r0 top
C198 "TAJA106M010RNJ" 3216-18 2931.33,855.38 r0 top
C199 "C1005X5R1A104K050BA" 0402 2898.26,1089.95 r0 top
C200 "06035C104KAT2A" 0603 1676.96,1604.4 r90 top
C201 "06035C104KAT2A" 0603 1638.26,679.95 r90 top
C202 "06035A101FAT2A" 0603 1456.96,1684.4 r270 top
C203 "06035A101FAT2A" 0603 1408.26,789.95 r270 top
C204 "C1608X7R1H103K080AA" 0603 2295.76,1829.44 r180 top
C205 "C1608X7R1H103K080AA" 0603 2145.78,1828.12 r180 top
C206 "C0603C470J5GACTU" 0603 1756.96,1634.4 r90 top
C207 "C0603C470J5GACTU" 0603 1718.26,699.95 r90 top
C208 "C1608X7R1H103K080AA" 0603 2131.55,1209.59 r180 top
C209 "C1608X7R1H103K080AA" 0603 2290.25,1209.59 r180 top
C210 "C1608X7R1H103K080AA" 0603 2448.46,1211.22 r180 top
C211 "06035A101FAT2A" 0603 1906.96,1684.4 r270 top
C212 "06035A101FAT2A" 0603 1878.26,819.95 r270 top
C213 "GRM21BR71A106KE51L" 0805_HV 2928.26,1903.26 r90 top
C214 "C3225X7R1C226K250AC" 1210_280 2788.26,1953.26 r0 top
C215 "C1608X7R1C105K080AC" 0603 2798.26,1843.26 r0 top
C216 "C1608X7R1H103K080AA" 0603 2598.26,1213.57 r180 top
C217 "C1608X7R1H103K080AA" 0603 2600.21,1829.95 r180 top
C218 "C1608X7R1H103K080AA" 0603 2450.21,1829.44 r180 top
C219 "C0603C470J5GACTU" 0603 1708.26,1234.4 r270 top
C220 "C0603C470J5GACTU" 0603 1746.96,2154.4 r270 top
C221 "06035A101FAT2A" 0603 1858.26,1128.3 r90 top
C222 "06035A101FAT2A" 0603 1886.96,2114.4 r90 top
C223 "GRM188R71C104KA01D" 0603 3128.25,1150 r180 top
C224 "C0603C470J5GACTU" 0603 1606.96,2154.4 r270 top
C225 "C0603C470J5GACTU" 0603 1568.26,1234.4 r270 top
C226 "06035A101FAT2A" 0603 1456.96,2094.4 r90 top
C227 "06035A101FAT2A" 0603 1418.26,1119.95 r90 top
C228 "06035C104KAT2A" 0603 5639.69,4618.98 r90 top
C229 "06035C104KAT2A" 0603 5639.69,5488.98 r90 top
C230 "C0603C470J5GACTU" 0603 5720.98,5158.98 r270 top
C231 "C0603C470J5GACTU" 0603 5719.69,6020 r270 top
C232 "LMK212B7105KD-T" 0805_HV 4671.89,5808.26 r0 top
C233 "TAJA106M010RNJ" 3216-18 4671.89,5918.26 r0 top
C234 "C1005X5R1A104K050BA" 0402 4651.89,5718.26 r0 top
C235 "LMK212B7105KD-T" 0805_HV 4483.19,5808.26 r180 top
C236 "TAJA106M010RNJ" 3216-18 4491.89,5918.26 r180 top
C237 "C1005X5R1A104K050BA" 0402 4501.89,5718.26 r180 top
C238 "06035C104KAT2A" 0603 5640,5210 r270 top
C239 "06035C104KAT2A" 0603 5639.69,6060 r270 top
C240 "06035A101FAT2A" 0603 5869.69,5048.98 r90 top
C241 "06035A101FAT2A" 0603 5869.69,5938.98 r90 top
C242 "C1608X7R1H103K080AA" 0603 5079.98,5000 r0 top
C243 "C1608X7R1H103K080AA" 0603 5219.98,5000 r0 top
C244 "C0603C470J5GACTU" 0603 5560.98,5168.98 r270 top
C245 "C0603C470J5GACTU" 0603 5559.69,6020 r270 top
C246 "C1608X7R1H103K080AA" 0603 5263.76,5628.26 r0 top
C247 "C1608X7R1H103K080AA" 0603 5117.81,5625.46 r0 top
C248 "06035A101FAT2A" 0603 5409.69,5058.98 r90 top
C249 "C1608X7R1H103K080AA" 0603 4971.81,5629.76 r0 top
C250 "06035A101FAT2A" 0603 5409.69,5938.98 r90 top
C251 "GRM21BR71A106KE51L" 0805_HV 4461,4903 r270 top
C252 "C3225X7R1C226K250AC" 1210_280 4611,4863 r180 top
C253 "C1608X7R1C105K080AC" 0603 4611,4973 r180 top
C254 "C1608X7R1H103K080AA" 0603 4827.81,5635.46 r0 top
C255 "C1608X7R1H103K080AA" 0603 4791.79,4998.7 r0 top
C256 "C1608X7R1H103K080AA" 0603 4940,5000 r0 top
C257 "C0603C470J5GACTU" 0603 5559.69,5518.98 r90 top
C258 "C0603C470J5GACTU" 0603 5559.69,4658.98 r90 top
C259 "06035A101FAT2A" 0603 5409.69,5648.98 r270 top
C260 "06035A101FAT2A" 0603 5420,4770 r270 top
C261 "GRM188R71C104KA01D" 0603 4300,5772.44 r0 top
C262 "C0603C470J5GACTU" 0603 5719.69,4663.43 r90 top
C263 "C0603C470J5GACTU" 0603 5719.69,5528.98 r90 top
C264 "06035A101FAT2A" 0603 5860,4780 r270 top
C265 "06035A101FAT2A" 0603 5869.69,5658.98 r270 top
C266 "GRM188R71C104KA01D" 0603 2848,4564 r90 top
C267 "GRM188R71C104KA01D" 0603 4007,1588 r90 top
C268 "GRM188R71C104KA01D" 0603 2859,2774 r90 top
C269 "GRM188R71C104KA01D" 0603 3928,3549 r0 top
C270 "GRM188R71C104KA01D" 0603 3058,855 r90 top
C271 "GRM188R71C104KA01D" 0603 4136,5339 r180 top
C272 "C1608X7R1C105K080AC" 0603 2223,6641 r0 top
C273 "GRM188R71C104KA01D" 0603 2079,6832 r180 top
D1 "DESD1P0RFWQ-7" SOT-323 1040,5490 r90 top
D2 "DESD1P0RFWQ-7" SOT-323 1050,4980 r90 top
D3 "DESD1P0RFWQ-7" SOT-323 1040,5370 r90 top
D4 "DESD1P0RFWQ-7" SOT-323 1010,4850 r90 top
D5 "DESD1P0RFWQ-7" SOT-323 1040,5240 r90 top
D6 "DESD1P0RFWQ-7" SOT-323 1040,5760 r90 top
D7 "LG M67K-G1J2-24-Z" LG_M67K_Green 3060,5150 r180 top
D8 "DESD1P0RFWQ-7" SOT-323 1040,5630 r90 top
D9 "DESD1P0RFWQ-7" SOT-323 1040,5120 r90 top
D10 "MBRM120ET1G" POWERMITE 3026.93,6244.57 r270 top
D11 "DZ2W15000L" SOD-123 5600,6688 r0 top
D12 "MMSZ5232B-7-F" SOD-123 4161.32,6152.76 r90 top
D13 "LG L29K-G2J1-24-Z" "LG L29K_GREEN" 4061.32,6272.76 r90 top
D14 "DZ2W15000L" SOD-123 5659,6393 r180 top
D15 "MBRM120ET1G" POWERMITE 3486.93,6594.57 r270 top
D16 "MMSZ4685T1G" SOD-123 3290,5310 r180 top
D17 "LG L29K-G2J1-24-Z" "LG L29K_GREEN" 3416.18,5450.39 r0 top
D18 "DESD1P0RFWQ-7" SOT-323 6182.05,1370 r90 top
D19 "DESD1P0RFWQ-7" SOT-323 6172.05,1910 r90 top
D20 "DESD1P0RFWQ-7" SOT-323 6182.05,1510 r90 top
D21 "DESD1P0RFWQ-7" SOT-323 6182.05,2040 r90 top
D22 "DESD1P0RFWQ-7" SOT-323 6182.05,1650 r90 top
D23 "DESD1P0RFWQ-7" SOT-323 6182.05,1100 r90 top
D24 "LG M67K-G1J2-24-Z" LG_M67K_Green 4073.35,1730 r0 top
D25 "DESD1P0RFWQ-7" SOT-323 6182.05,1240 r90 top
D26 "DESD1P0RFWQ-7" SOT-323 6172.05,1780 r90 top
D27 "DESD1P0RFWQ-7" SOT-323 1012.36,3590 r90 top
D28 "DESD1P0RFWQ-7" SOT-323 1032.36,3090 r90 top
D29 "DESD1P0RFWQ-7" SOT-323 1012.36,3470 r90 top
D30 "DESD1P0RFWQ-7" SOT-323 1012.36,2960 r90 top
D31 "DESD1P0RFWQ-7" SOT-323 1012.36,3340 r90 top
D32 "DESD1P0RFWQ-7" SOT-323 1012.36,3850 r90 top
D33 "LG M67K-G1J2-24-Z" LG_M67K_Green 3072.36,3320 r180 top
D34 "DESD1P0RFWQ-7" SOT-323 1012.36,3720 r90 top
D35 "DESD1P0RFWQ-7" SOT-323 1012.36,3220 r90 top
D36 "DESD1P0RFWQ-7" SOT-323 6152.05,3260 r90 top
D37 "DESD1P0RFWQ-7" SOT-323 6142.05,3800 r90 top
D38 "DESD1P0RFWQ-7" SOT-323 6142.05,3390 r90 top
D39 "DESD1P0RFWQ-7" SOT-323 6142.05,3930 r90 top
D40 "DESD1P0RFWQ-7" SOT-323 6142.05,3530 r90 top
D41 "DESD1P0RFWQ-7" SOT-323 6152.05,2990 r90 top
D42 "LG M67K-G1J2-24-Z" LG_M67K_Green 4122.05,3600 r0 top
D43 "DESD1P0RFWQ-7" SOT-323 6152.05,3120 r90 top
D44 "DESD1P0RFWQ-7" SOT-323 6142.05,3670 r90 top
D45 "DESD1P0RFWQ-7" SOT-323 1008.26,1629.95 r90 top
D46 "DESD1P0RFWQ-7" SOT-323 1038.25,1109.96 r90 top
D47 "DESD1P0RFWQ-7" SOT-323 1008.25,1509.96 r90 top
D48 "DESD1P0RFWQ-7" SOT-323 1028.25,979.96 r90 top
D49 "DESD1P0RFWQ-7" SOT-323 1008.25,1369.96 r90 top
D50 "DESD1P0RFWQ-7" SOT-323 1008.25,1909.96 r90 top
D51 "LG M67K-G1J2-24-Z" LG_M67K_Green 3256.36,1374.17 r180 top
D52 "DESD1P0RFWQ-7" SOT-323 1008.26,1769.95 r90 top
D53 "DESD1P0RFWQ-7" SOT-323 1018.25,1239.96 r90 top
D54 "DESD1P0RFWQ-7" SOT-323 6152.05,5128.98 r90 top
D55 "DESD1P0RFWQ-7" SOT-323 6152.05,5678.98 r90 top
D56 "DESD1P0RFWQ-7" SOT-323 6152.05,5258.98 r90 top
D57 "DESD1P0RFWQ-7" SOT-323 6152.05,5828.98 r90 top
D58 "DESD1P0RFWQ-7" SOT-323 6152.05,5398.98 r90 top
D59 "DESD1P0RFWQ-7" SOT-323 6162.05,4838.98 r90 top
D60 "LG M67K-G1J2-24-Z" LG_M67K_Green 4140,5542.44 r0 top
D61 "DESD1P0RFWQ-7" SOT-323 6152.05,4978.98 r90 top
D62 "DESD1P0RFWQ-7" SOT-323 6152.05,5538.98 r90 top
FB1 "MMZ1608B102CTA00" MMZ1608_095 3296.18,5610.39 r270 top
FID1 "Fiducial" Fiducial10-20 250,6220 r0 top
FID2 "Fiducial" Fiducial10-20 290,640 r0 top
FID3 "Fiducial" Fiducial10-20 6590,620 r0 top
H1 "NY PMS 440 0025 PH" "NY PMS 440 0025 PH" 450,6570 r0 top locked
H2 "NY PMS 440 0025 PH" "NY PMS 440 0025 PH" 6710,6580 r0 top locked
H3 "NY PMS 440 0025 PH" "NY PMS 440 0025 PH" 470,210 r0 top locked
H4 "NY PMS 440 0025 PH" "NY PMS 440 0025 PH" 6700,210 r0 top locked
H5 "1902C" Keystone_1902C#1 450,6570 r180 bottom locked
H6 "1902C" Keystone_1902C#1 6710,6580 r180 bottom locked
H7 "1902C" Keystone_1902C#1 470,210 r180 bottom locked
H8 "1902C" Keystone_1902C#1 6700,210 r180 bottom locked
H9 "NY PMS 440 0025 PH" "NY PMS 440 0025 PH" 4064,4363 r0 top
H10 "NY PMS 440 0025 PH" "NY PMS 440 0025 PH" 4191,2588 r0 top
H11 "1902C" Keystone_1902C#2 4190.77,2588.01 r180 bottom
H12 "1902C" Keystone_1902C#2 4063.77,4363.01 r180 bottom
J1 "SBH11-PBPC-D10-ST-BK" Sullins_SBH11-xxxC-D10-ST 710,5430 r180 top
J2 "5-146280-2" TSW-102-07-G-S 2730,6850 r180 top
J3 "PJ-002AH-SMT-TR" CUI_PJ-002AH-SMT 1660,6650 r270 top
J4 "5-146280-2" TSW-102-07-G-S 3460,6160 r90 top
J5 "ZSS-120-01-L-D-529" CONN_ZSS-120-01-L-D-529 3690,460 r180 top
J6 "SBH11-PBPC-D10-ST-BK" Sullins_SBH11-xxxC-D10-ST 6482.05,1530 r0 top
J7 "SBH11-PBPC-D10-ST-BK" Sullins_SBH11-xxxC-D10-ST 712.36,3530 r180 top
J8 "SBH11-PBPC-D10-ST-BK" Sullins_SBH11-xxxC-D10-ST 6452.05,3400 r0 top
J9 "SBH11-PBPC-D10-ST-BK" Sullins_SBH11-xxxC-D10-ST 708.26,1529.95 r180 top
J10 "SBH11-PBPC-D10-ST-BK" Sullins_SBH11-xxxC-D10-ST 6452.05,5248.98 r0 top
J11 "PEC02SAAN" CONN_PEC02SAAN 4289,6622 r90 top
J12 "PEC02SAAN" CONN_PEC02SAAN 4701,6297 r90 top
L1 "VLF504012MT-4R7M" VLF504012MT 2856.93,6124.57 r90 top
L2 "VLF504012MT-4R7M" VLF504012MT 3680,6724.57 r270 top
LBL1 "Size: 0.65\" x 0.20 \"" Label_650x200 1408,167 r0 top
Logo1 "Texas Instruments" TI_Stacked_Overlay_Small 5680,270 r0 top
Logo2 "Pb-Free Symbol" Pb-Free_Overlay_Small 2050,290 r0 top
Logo3 "FCC disclaimer" FCC_disclaimer 2350,3380 r0 top
Q1 "CSD17571Q2" DQK0006C 3150,5030 r0 top
Q2 "CSD17571Q2" DQK0006C 2210,6211.97 r0 top
Q3 "CSD17571Q2" DQK0006C 4010,1850 r180 top
Q4 "CSD17571Q2" DQK0006C 3162.36,3200 r0 top
Q5 "CSD17571Q2" DQK0006C 4052.04,3710 r180 top
Q6 "CSD17571Q2" DQK0006C 3350,1250 r0 top
Q7 "CSD17571Q2" DQK0006C 4069.99,5652.43 r180 top
R1 "CRCW060351K0JNEA" 0603 1310,5420.31 r90 top
R2 "CRCW060351K0JNEA" 0603 1390,5470.31 r90 top
R3 "CRCW060351K0JNEA" 0603 1312,4603.69 r90 top
R4 "CRCW060351K0JNEA" 0603 1392,4653.69 r90 top
R5 "CRCW06030000Z0EA" 0603 400,5580 r0 top
R6 "CRCW06030000Z0EA" 0603 400,5680 r0 top
R7 "CRCW06030000Z0EA" 0603 400,4980 r0 top
R8 "CRCW06030000Z0EA" 0603 400,5080 r0 top
R9 "CRCW06030000Z0EA" 0603 400,5180 r0 top
R10 "CRCW06030000Z0EA" 0603 400,5280 r0 top
R11 "CRCW06030000Z0EA" 0603 400,5380 r0 top
R12 "CRCW06030000Z0EA" 0603 400,5480 r0 top
R13 "CRCW0402357RFKED" 0402 2125.76,5710 r270 top
R14 "CRCW0402357RFKED" 0402 2045.76,5710 r270 top
R15 "CRCW0402357RFKED" 0402 1975.78,5710 r270 top
R16 "RC0603FR-0747KL" 0603 2900,5519.95 r0 top
R17 "CRCW0402357RFKED" 0402 1895.78,5710 r270 top
R18 "CRCW060351K0JNEA" 0603 1740,5440.31 r90 top
R19 "CRCW060351K0JNEA" 0603 1670,5470.31 r90 top
R20 "CRCW060351K0JNEA" 0603 1752,4613.69 r90 top
R21 "CRCW060351K0JNEA" 0603 1672,4653.69 r90 top
R22 "CRCW0402357RFKED" 0402 1963.5,4895.96 r90 top
R23 "RC0603FR-0747KL" 0603 2910,5339.95 r0 top
R24 "CRCW0402357RFKED" 0402 1883.5,4895.96 r90 top
R25 "CRCW0402357RFKED" 0402 2123.52,4895.96 r90 top
R26 "CRCW0402357RFKED" 0402 2043.52,4895.96 r90 top
R27 "CRCW0402357RFKED" 0402 2280,4897.6 r90 top
R28 "CRCW0402357RFKED" 0402 2201.73,4900 r90 top
R29 "CRCW0402357RFKED" 0402 2430,4893.57 r90 top
R30 "CRCW0402357RFKED" 0402 2348.26,4893.57 r90 top
R31 "CRCW0402357RFKED" 0402 2430,5709.44 r270 top
R32 "CRCW0402357RFKED" 0402 2350,5709.44 r270 top
R33 "CRCW0402357RFKED" 0402 2280.21,5710 r270 top
R34 "CRCW0402357RFKED" 0402 2200,5707.16 r270 top
R35 "CRCW060351K0JNEA" 0603 1752,5203.69 r270 top
R36 "CRCW060351K0JNEA" 0603 1672,5173.69 r270 top
R37 "CRCW060351K0JNEA" 0603 1750,5990.31 r270 top
R38 "CRCW060351K0JNEA" 0603 1670,5970.31 r270 top
R39 "CRCW0603300RJNEA" 0603 2910,5150 r180 top
R40 "CRCW060351K0JNEA" 0603 1300,6010.31 r270 top
R41 "CRCW060351K0JNEA" 0603 1380,5970.31 r270 top
R42 "RMCF0603ZT0R00" 0603 2790,5070 r270 top
R43 "CRCW0603300RJNEA" 0603 3050,5020 r270 top
R44 "CRCW060351K0JNEA" 0603 1312,5223.69 r270 top
R45 "CRCW060351K0JNEA" 0603 1382,5173.69 r270 top
R46 "CRCW12060000Z0EA" 1206 2796.93,6344.57 r90 top
R47 "CRCW06030000Z0EA" 0603 2686.93,6454.57 r270 top
R48 "RC0603FR-07820RL" 0603 4061.32,6142.76 r270 top
R49 "CRCW0603576KFKEA" 0603 2936.93,6454.57 r270 top
R50 "RG1608P-4992-B-T5" 0603 3026.93,6454.57 r270 top
R51 "CRCW06030000Z0EA" 0603 3050,6680 r180 top
R52 "CRCW0603620KFKEA" 0603 3190,6803.27 r90 top
R53 "CRCW06030000Z0EA" 0603 3366.93,6724.57 r270 top
R54 "RG1608P-4992-B-T5" 0603 3120,6803.27 r270 top
R55 "RG1608P-4992-B-T5" 0603 3270,6803.27 r90 top
R56 "CR0603-J/-1R0ELF" 0603 3326.93,6324.57 r180 top
R57 "CRCW06031K00JNEA" 0603 2916.93,6594.57 r180 top
R58 "CRCW06030000Z0EA" 0603 5290,6660 r90 top
R59 "CRCW06030000Z0EA" 0603 4850,6580 r0 top
R60 "CRCW0603274KFKEA" 0603 5285.39,6520 r90 top
R61 "CRCW06030000Z0EA" 0603 4860,6310 r0 top
R62 "CRCW0603274KFKEA" 0603 5285.39,6370 r270 top
R63 "CRCW060331K6FKEA" 0603 5480,6500 r180 top
R64 "CRCW0603300RJNEA" 0603 3386.18,5600.39 r90 top
R65 "CRCW06030000Z0EA" 0603 4850,6500 r0 top
R66 "CRCW060327K4FKEA" 0603 5480,6400 r180 top
R67 "CRCW06030000Z0EA" 0603 5455.39,6290 r270 top
R68 "CRCW0603300RJNEA" 0603 2080,6211.97 r180 top
R69 "CRCW04020000Z0ED" 0402 1694,5774 r180 top
R70 "CRCW08050000Z0EA" 0805_HV 3326.18,5730.39 r180 top
R71 "RMCF0603ZT0R00" 0603 2310,6221.97 r270 top
R72 "CRCW0603300RJNEA" 0603 2080,6120.31 r180 top
R73 "CRCW060351K0JNEA" 0603 5842.05,1418.74 r270 top
R74 "CRCW060351K0JNEA" 0603 5763.35,1367.24 r270 top
R75 "CRCW060351K0JNEA" 0603 5840,2220 r270 top
R76 "CRCW060351K0JNEA" 0603 5760,2220 r270 top
R77 "CRCW06030000Z0EA" 0603 6782.05,1380 r180 top
R78 "CRCW06030000Z0EA" 0603 6782.05,1280 r180 top
R79 "CRCW06030000Z0EA" 0603 6782.05,1980 r180 top
R80 "CRCW06030000Z0EA" 0603 6782.05,1880 r180 top
R81 "CRCW06030000Z0EA" 0603 6782.05,1780 r180 top
R82 "CRCW06030000Z0EA" 0603 6782.05,1680 r180 top
R83 "CRCW06030000Z0EA" 0603 6782.05,1580 r180 top
R84 "CRCW06030000Z0EA" 0603 6782.05,1480 r180 top
R85 "CRCW0402357RFKED" 0402 4970,1103.62 r90 top
R86 "CRCW0402357RFKED" 0402 5040,1103.62 r90 top
R87 "CRCW0402357RFKED" 0402 5110,1103.62 r90 top
R88 "RC0603FR-0747KL" 0603 4252.05,1470 r180 top
R89 "CRCW0402357RFKED" 0402 5180,1103.62 r90 top
R90 "CRCW060351K0JNEA" 0603 5362.05,1397.24 r270 top
R91 "CRCW060351K0JNEA" 0603 5442.05,1377.24 r270 top
R92 "CRCW060351K0JNEA" 0603 5380,2220 r270 top
R93 "CRCW060351K0JNEA" 0603 5470,2220 r270 top
R94 "CRCW0402357RFKED" 0402 5164.45,1932.8 r270 top
R95 "RC0603FR-0747KL" 0603 4250,1340 r180 top
R96 "CRCW0402357RFKED" 0402 5234.45,1932.8 r270 top
R97 "CRCW0402357RFKED" 0402 5018.5,1930 r270 top
R98 "CRCW0402357RFKED" 0402 5088.5,1930 r270 top
R99 "CRCW0402357RFKED" 0402 4872.5,1932.8 r270 top
R100 "CRCW0402357RFKED" 0402 4942.5,1932.8 r270 top
R101 "CRCW0402357RFKED" 0402 4722.5,1932.8 r270 top
R102 "CRCW0402357RFKED" 0402 4792.5,1932.8 r270 top
R103 "CRCW0402357RFKED" 0402 4680,1102.32 r90 top
R104 "CRCW0402357RFKED" 0402 4760,1102.32 r90 top
R105 "CRCW0402357RFKED" 0402 4828.21,1103.62 r90 top
R106 "CRCW0402357RFKED" 0402 4898.21,1103.62 r90 top
R107 "CRCW060351K0JNEA" 0603 5382.05,1701.63 r90 top
R108 "CRCW060351K0JNEA" 0603 5460,1710 r90 top
R109 "CRCW060351K0JNEA" 0603 5370.73,860 r90 top
R110 "CRCW060351K0JNEA" 0603 5450.73,884.45 r90 top
R111 "CRCW0603300RJNEA" 0603 4213.35,1740 r0 top
R112 "CRCW060351K0JNEA" 0603 5826,869 r90 top
R113 "CRCW060351K0JNEA" 0603 5750.73,884.45 r90 top
R114 "RMCF0603ZT0R00" 0603 4352.05,1800 r90 top
R115 "CRCW0603300RJNEA" 0603 4103.35,1860 r90 top
R116 "CRCW060351K0JNEA" 0603 5840,1700 r90 top
R117 "CRCW060351K0JNEA" 0603 5760,1710 r90 top
R118 "CRCW060351K0JNEA" 0603 1292.36,3620 r90 top
R119 "CRCW060351K0JNEA" 0603 1372.36,3640 r90 top
R120 "CRCW060351K0JNEA" 0603 1282.36,2760 r90 top
R121 "CRCW060351K0JNEA" 0603 1362.36,2790 r90 top
R122 "CRCW06030000Z0EA" 0603 422.36,3680 r0 top
R123 "CRCW06030000Z0EA" 0603 422.36,3780 r0 top
R124 "CRCW06030000Z0EA" 0603 422.36,3080 r0 top
R125 "CRCW06030000Z0EA" 0603 422.36,3180 r0 top
R126 "CRCW06030000Z0EA" 0603 422.36,3280 r0 top
R127 "CRCW06030000Z0EA" 0603 422.36,3380 r0 top
R128 "CRCW06030000Z0EA" 0603 422.36,3480 r0 top
R129 "CRCW06030000Z0EA" 0603 422.36,3580 r0 top
R130 "CRCW0402357RFKED" 0402 2145.55,3878.12 r270 top
R131 "CRCW0402357RFKED" 0402 2065.55,3880 r270 top
R132 "CRCW0402357RFKED" 0402 2004.45,3879.26 r270 top
R133 "RC0603FR-0747KL" 0603 2912.36,3689.95 r0 top
R134 "CRCW0402357RFKED" 0402 1924.45,3878.7 r270 top
R135 "CRCW060351K0JNEA" 0603 1742.36,3620 r90 top
R136 "CRCW060351K0JNEA" 0603 1672.36,3640 r90 top
R137 "CRCW060351K0JNEA" 0603 1742.36,2740 r90 top
R138 "CRCW060351K0JNEA" 0603 1662.36,2790 r90 top
R139 "CRCW0402357RFKED" 0402 1975.86,3065.96 r90 top
R140 "RC0603FR-0747KL" 0603 2922.36,3509.95 r0 top
R141 "CRCW0402357RFKED" 0402 1895.86,3065.96 r90 top
R142 "CRCW0402357RFKED" 0402 2135.88,3065.97 r90 top
R143 "CRCW0402357RFKED" 0402 2055.88,3065.96 r90 top
R144 "CRCW0402357RFKED" 0402 2294.09,3067.6 r90 top
R145 "CRCW0402357RFKED" 0402 2214.09,3070 r90 top
R146 "CRCW0402357RFKED" 0402 2442.36,3063.57 r90 top
R147 "CRCW0402357RFKED" 0402 2360.62,3063.57 r90 top
R148 "CRCW0402357RFKED" 0402 2442.36,3879.44 r270 top
R149 "CRCW0402357RFKED" 0402 2362.57,3879.44 r270 top
R150 "CRCW0402357RFKED" 0402 2292.57,3877.16 r270 top
R151 "CRCW0402357RFKED" 0402 2212.57,3877.16 r270 top
R152 "CRCW060351K0JNEA" 0603 1742.36,3350 r270 top
R153 "CRCW060351K0JNEA" 0603 1662.36,3320 r270 top
R154 "CRCW060351K0JNEA" 0603 1752.36,4190 r270 top
R155 "CRCW060351K0JNEA" 0603 1672.36,4160 r270 top
R156 "CRCW0603300RJNEA" 0603 2922.36,3320 r180 top
R157 "CRCW060351K0JNEA" 0603 1302.36,4200 r270 top
R158 "CRCW060351K0JNEA" 0603 1382.36,4160 r270 top
R159 "RMCF0603ZT0R00" 0603 2802.36,3240 r270 top
R160 "CRCW0603300RJNEA" 0603 3062.36,3190 r270 top
R161 "CRCW060351K0JNEA" 0603 1282.36,3350 r270 top
R162 "CRCW060351K0JNEA" 0603 1362.36,3320 r270 top
R163 "CRCW060351K0JNEA" 0603 5852.05,3280 r270 top
R164 "CRCW060351K0JNEA" 0603 5772.05,3240 r270 top
R165 "CRCW060351K0JNEA" 0603 5872.05,4130 r270 top
R166 "CRCW060351K0JNEA" 0603 5782.05,4110 r270 top
R167 "CRCW06030000Z0EA" 0603 6742.05,3250 r180 top
R168 "CRCW06030000Z0EA" 0603 6742.05,3150 r180 top
R169 "CRCW06030000Z0EA" 0603 6742.05,3850 r180 top
R170 "CRCW06030000Z0EA" 0603 6742.05,3750 r180 top
R171 "CRCW06030000Z0EA" 0603 6742.05,3650 r180 top
R172 "CRCW06030000Z0EA" 0603 6742.05,3550 r180 top
R173 "CRCW06030000Z0EA" 0603 6742.05,3450 r180 top
R174 "CRCW06030000Z0EA" 0603 6742.05,3350 r180 top
R175 "CRCW0402357RFKED" 0402 5031.81,2960 r90 top
R176 "CRCW0402357RFKED" 0402 5101.81,2960 r90 top
R177 "CRCW0402357RFKED" 0402 5171.81,2960 r90 top
R178 "RC0603FR-0747KL" 0603 4322.05,3340 r180 top
R179 "CRCW0402357RFKED" 0402 5241.81,2960 r90 top
R180 "CRCW060351K0JNEA" 0603 5392.05,3270 r270 top
R181 "CRCW060351K0JNEA" 0603 5472.05,3250 r270 top
R182 "CRCW060351K0JNEA" 0603 5412.05,4130 r270 top
R183 "CRCW060351K0JNEA" 0603 5492.05,4120 r270 top
R184 "CRCW0402357RFKED" 0402 5221.95,3791.81 r270 top
R185 "RC0603FR-0747KL" 0603 4322.05,3220 r180 top
R186 "CRCW0402357RFKED" 0402 5291.95,3791.81 r270 top
R187 "CRCW0402357RFKED" 0402 5076,3789.01 r270 top
R188 "CRCW0402357RFKED" 0402 5146,3789.01 r270 top
R189 "CRCW0402357RFKED" 0402 4930,3791.81 r270 top
R190 "CRCW0402357RFKED" 0402 5000,3791.81 r270 top
R191 "CRCW0402357RFKED" 0402 4780,3791.81 r270 top
R192 "CRCW0402357RFKED" 0402 4850,3791.81 r270 top
R193 "CRCW0402357RFKED" 0402 4741.81,2958.7 r90 top
R194 "CRCW0402357RFKED" 0402 4821.81,2958.7 r90 top
R195 "CRCW0402357RFKED" 0402 4890.02,2960 r90 top
R196 "CRCW0402357RFKED" 0402 4960.02,2960 r90 top
R197 "CRCW060351K0JNEA" 0603 5412.05,3560 r90 top
R198 "CRCW060351K0JNEA" 0603 5492.05,3590 r90 top
R199 "CRCW060351K0JNEA" 0603 5392.05,2700 r90 top
R200 "CRCW060351K0JNEA" 0603 5475,2724.98 r90 top
R201 "CRCW0603300RJNEA" 0603 4262.05,3610 r0 top
R202 "CRCW060351K0JNEA" 0603 5850,2720 r90 top
R203 "CRCW060351K0JNEA" 0603 5772.05,2724.45 r90 top
R204 "RMCF0603ZT0R00" 0603 4402.05,3660 r90 top
R205 "CRCW0603300RJNEA" 0603 4152.05,3730 r90 top
R206 "CRCW060351K0JNEA" 0603 5882.05,3570 r90 top
R207 "CRCW060351K0JNEA" 0603 5792.05,3590 r90 top
R208 "CRCW060351K0JNEA" 0603 1426.96,1574.4 r0 top
R209 "CRCW060351K0JNEA" 0603 1536.96,1634.4 r90 top
R210 "CRCW060351K0JNEA" 0603 1358.26,679.95 r0 top
R211 "CRCW060351K0JNEA" 0603 1488.26,699.95 r90 top
R212 "CRCW06030000Z0EA" 0603 418.26,1679.95 r0 top
R213 "CRCW06030000Z0EA" 0603 418.26,1779.95 r0 top
R214 "CRCW06030000Z0EA" 0603 418.26,1079.95 r0 top
R215 "CRCW06030000Z0EA" 0603 418.26,1179.95 r0 top
R216 "CRCW06030000Z0EA" 0603 418.26,1279.95 r0 top
R217 "CRCW06030000Z0EA" 0603 418.26,1379.95 r0 top
R218 "CRCW06030000Z0EA" 0603 418.26,1479.95 r0 top
R219 "CRCW06030000Z0EA" 0603 418.26,1579.95 r0 top
R220 "CRCW0402357RFKED" 0402 2335.76,1929.44 r270 top
R221 "CRCW0402357RFKED" 0402 2255.76,1929.44 r270 top
R222 "CRCW0402357RFKED" 0402 2185.78,1928.12 r270 top
R223 "RC0603FR-0747KL" 0603 3108.26,1739.95 r0 top
R224 "CRCW0402357RFKED" 0402 2105.78,1928.12 r270 top
R225 "CRCW060351K0JNEA" 0603 1906.96,1534.4 r90 top
R226 "CRCW060351K0JNEA" 0603 1826.96,1634.4 r90 top
R227 "CRCW060351K0JNEA" 0603 1888.26,639.95 r90 top
R228 "CRCW060351K0JNEA" 0603 1798.26,699.95 r90 top
R229 "CRCW0402357RFKED" 0402 2173.5,1115.96 r90 top
R230 "RC0603FR-0747KL" 0603 3118.26,1559.95 r0 top
R231 "CRCW0402357RFKED" 0402 2093.5,1115.96 r90 top
R232 "CRCW0402357RFKED" 0402 2333.52,1115.96 r90 top
R233 "CRCW0402357RFKED" 0402 2253.52,1115.96 r90 top
R234 "CRCW0402357RFKED" 0402 2491.73,1117.6 r90 top
R235 "CRCW0402357RFKED" 0402 2411.73,1117.6 r90 top
R236 "CRCW0402357RFKED" 0402 2638.26,1113.57 r90 top
R237 "CRCW0402357RFKED" 0402 2558.26,1113.57 r90 top
R238 "CRCW0402357RFKED" 0402 2640.21,1929.44 r270 top
R239 "CRCW0402357RFKED" 0402 2560.21,1929.44 r270 top
R240 "CRCW0402357RFKED" 0402 2490.21,1927.16 r270 top
R241 "CRCW0402357RFKED" 0402 2410.21,1927.16 r270 top
R242 "CRCW060351K0JNEA" 0603 1858.26,1288.3 r270 top
R243 "CRCW060351K0JNEA" 0603 1778.26,1234.4 r270 top
R244 "CRCW060351K0JNEA" 0603 1886.96,2254.4 r270 top
R245 "CRCW060351K0JNEA" 0603 1816.96,2154.4 r270 top
R246 "CRCW0603300RJNEA" 0603 3126.36,1374.17 r180 top
R247 "CRCW060351K0JNEA" 0603 1426.96,2204.4 r0 top
R248 "CRCW060351K0JNEA" 0603 1536.96,2154.4 r270 top
R249 "RMCF0603ZT0R00" 0603 3000,1290 r270 top
R250 "CRCW0603300RJNEA" 0603 3248.25,1250 r270 top
R251 "CRCW060351K0JNEA" 0603 1388.26,1239.95 r0 top
R252 "CRCW060351K0JNEA" 0603 1498.26,1234.4 r270 top
R253 "CRCW060351K0JNEA" 0603 5869.69,5198.98 r270 top
R254 "CRCW060351K0JNEA" 0603 5790.98,5158.98 r270 top
R255 "CRCW060351K0JNEA" 0603 5869.69,6088.98 r270 top
R256 "CRCW060351K0JNEA" 0603 5789.69,6020 r270 top
R257 "CRCW06030000Z0EA" 0603 6762.05,5098.98 r180 top
R258 "CRCW06030000Z0EA" 0603 6762.05,4998.98 r180 top
R259 "CRCW06030000Z0EA" 0603 6762.05,5698.98 r180 top
R260 "CRCW06030000Z0EA" 0603 6762.05,5598.98 r180 top
R261 "CRCW06030000Z0EA" 0603 6762.05,5498.98 r180 top
R262 "CRCW06030000Z0EA" 0603 6762.05,5398.98 r180 top
R263 "CRCW06030000Z0EA" 0603 6762.05,5298.98 r180 top
R264 "CRCW06030000Z0EA" 0603 6762.05,5198.98 r180 top
R265 "CRCW0402357RFKED" 0402 5041.79,4900 r90 top
R266 "CRCW0402357RFKED" 0402 5111.79,4900 r90 top
R267 "CRCW0402357RFKED" 0402 5181.79,4900 r90 top
R268 "RC0603FR-0747KL" 0603 4331.89,5278.26 r180 top
R269 "CRCW0402357RFKED" 0402 5259.9,4894.18 r90 top
R270 "CRCW060351K0JNEA" 0603 5409.69,5208.98 r270 top
R271 "CRCW060351K0JNEA" 0603 5490.98,5168.98 r270 top
R272 "CRCW060351K0JNEA" 0603 5409.69,6078.98 r270 top
R273 "CRCW060351K0JNEA" 0603 5489.69,6020 r270 top
R274 "CRCW0402357RFKED" 0402 5233.76,5728.26 r270 top
R275 "RC0603FR-0747KL" 0603 4331.89,5158.26 r180 top
R276 "CRCW0402357RFKED" 0402 5299.92,5732.44 r270 top
R277 "CRCW0402357RFKED" 0402 5087.81,5725.46 r270 top
R278 "CRCW0402357RFKED" 0402 5157.81,5725.46 r270 top
R279 "CRCW0402357RFKED" 0402 4941.81,5728.26 r270 top
R280 "CRCW0402357RFKED" 0402 5011.81,5728.26 r270 top
R281 "CRCW0402357RFKED" 0402 4791.81,5728.26 r270 top
R282 "CRCW0402357RFKED" 0402 4861.81,5728.26 r270 top
R283 "CRCW0402357RFKED" 0402 4751.79,4898.7 r90 top
R284 "CRCW0402357RFKED" 0402 4831.79,4898.7 r90 top
R285 "CRCW0402357RFKED" 0402 4900,4900 r90 top
R286 "CRCW0402357RFKED" 0402 4970,4900 r90 top
R287 "CRCW060351K0JNEA" 0603 5409.69,5488.98 r90 top
R288 "CRCW060351K0JNEA" 0603 5489.69,5518.98 r90 top
R289 "CRCW060351K0JNEA" 0603 5410,4630 r90 top
R290 "CRCW060351K0JNEA" 0603 5489.69,4658.98 r90 top
R291 "CRCW0603300RJNEA" 0603 4300,5542.44 r0 top
R292 "CRCW060351K0JNEA" 0603 5860,4640 r90 top
R293 "CRCW060351K0JNEA" 0603 5789.69,4663.43 r90 top
R294 "RMCF0603ZT0R00" 0603 4420,5602.44 r90 top
R295 "CRCW0603300RJNEA" 0603 4170,5672.44 r90 top
R296 "CRCW060351K0JNEA" 0603 5869.69,5508.98 r90 top
R297 "CRCW060351K0JNEA" 0603 5789.69,5528.98 r90 top
R298 "CRCW06030000Z0EA" 0603 2580,4979.95 r270 top
R299 "CRCW06030000Z0EA" 0603 2658.26,4980 r270 top
R300 "CRCW06030000Z0EA" 0603 4552.05,1800 r90 top
R301 "CRCW06030000Z0EA" 0603 4452.05,1810 r90 top
R302 "CRCW06030000Z0EA" 0603 2592.36,3149.95 r270 top
R303 "CRCW06030000Z0EA" 0603 2670.62,3150 r270 top
R304 "CRCW06030000Z0EA" 0603 4622.05,3670 r90 top
R305 "CRCW06030000Z0EA" 0603 4513.35,3670 r90 top
R306 "CRCW06030000Z0EA" 0603 2788.26,1199.95 r270 top
R307 "CRCW06030000Z0EA" 0603 2868.26,1199.95 r270 top
R308 "CRCW06030000Z0EA" 0603 4631.89,5608.26 r90 top
R309 "CRCW06030000Z0EA" 0603 4523.19,5608.26 r90 top
R310 "CRCW04020000Z0ED" 0402 1704,4970 r180 top
R311 "CRCW04020000Z0ED" 0402 1702,5676 r180 top
R312 "CRCW04020000Z0ED" 0402 1338,4872 r0 top
R313 "CRCW04020000Z0ED" 0402 2540,5509 r270 top
R314 "CRCW04020000Z0ED" 0402 5800,1098 r180 top
R315 "CRCW04020000Z0ED" 0402 5841,1936 r180 top
R316 "CRCW04020000Z0ED" 0402 5776,1178 r180 top
R317 "CRCW04020000Z0ED" 0402 5841,1989 r180 top
R318 "CRCW04020000Z0ED" 0402 4580,1287.19 r90 top
R319 "CRCW04020000Z0ED" 0402 1310,3945 r0 top
R320 "CRCW04020000Z0ED" 0402 1304,3075 r0 top
R321 "CRCW04020000Z0ED" 0402 1311,3889 r0 top
R322 "CRCW04020000Z0ED" 0402 1304,3022 r0 top
R323 "CRCW04020000Z0ED" 0402 2550,3702 r270 top
R324 "CRCW04020000Z0ED" 0402 5843,2957 r180 top
R325 "CRCW04020000Z0ED" 0402 5854,3810 r180 top
R326 "CRCW04020000Z0ED" 0402 5841,3018 r180 top
R327 "CRCW04020000Z0ED" 0402 5855,3870 r180 top
R328 "CRCW04020000Z0ED" 0402 4650,3155 r90 top
R329 "CRCW04020000Z0ED" 0402 1441,1957 r0 top
R330 "CRCW04020000Z0ED" 0402 1429,998 r0 top
R331 "CRCW04020000Z0ED" 0402 1442,1837 r0 top
R332 "CRCW04020000Z0ED" 0402 1428,925 r0 top
R333 "CRCW04020000Z0ED" 0402 2743,1750 r270 top
R334 "CRCW04020000Z0ED" 0402 5845,4890 r180 top
R335 "CRCW04020000Z0ED" 0402 5864,5768 r180 top
R336 "CRCW04020000Z0ED" 0402 5845,4947 r180 top
R337 "CRCW04020000Z0ED" 0402 5864,5827 r180 top
R338 "CRCW04020000Z0ED" 0402 4658,5080 r90 top
TP1 "+5V" Keystone5010 4440,6110.81 r180 top
TP2 "Suggest using a net name here" Mill-Max_0253-0-15-15-30-27-10-0 2526.93,6804.57 r0 top
TP3 "" Keystone5126 4021.32,6422.76 r180 top
TP4 "Suggest using a net name here" Mill-Max_0253-0-15-15-30-27-10-0 3550,5968 r0 top
TP5 "" Keystone5010 3456.93,6404.57 r0 top
TP6 "Suggest using a net name here" Mill-Max_0253-0-15-15-30-27-10-0 3500,5170 r180 top
TP7 "Suggest using a net name here" Mill-Max_0253-0-15-15-30-27-10-0 5405.39,6690 r0 top
TP8 "Suggest using a net name here" Mill-Max_0253-0-15-15-30-27-10-0 5310,6240 r0 top
U1 "OPA4197IPWR" PW0014A_N 1530,5720.31 r270 top
U2 "OPA4197IPWR" PW0014A_N 1530,4909.69 r270 top
U3 "ADS8688IDBT" DBT0038A_N 2538.26,5290 r270 top
U4 "SN74LVC1G17DCKR" DCK0005A_N 2920,5020 r0 top
U5 "TPS22914YFP" YFP0004ABAB 2100,6730.32 r270 top
U6 "LP2992AILD-5.0/NOPB" LDE06A 4441.32,6302.76 r180 top
U7 "TPS65131RGET" RGE0024B 3196.93,6494.57 r90 top
U8 "TPS7A3901DSC" DSC0010J 5085.39,6440 r0 top
U9 "TPS7A6533QKVURQ1" KVU0003A_N 3660,5550 r270 top
U10 "SN74LVC1G17DCKR" DCK0005A_N 2950,4589 r270 top
U11 "SN74LVC1G17DCKR" DCK0005A_N 2220,6061.97 r270 top
U12 "OPA4197IPWR" PW0014A_N 5600.73,1140 r90 top
U13 "OPA4197IPWR" PW0014A_N 5612.05,1960 r90 top
U14 "ADS8688IDBT" DBT0038A_N 4582.05,1520 r90 top
U15 "SN74LVC1G17DCKR" DCK0005A_N 4223.35,1860 r180 top
U16 "OPA4197IPWR" PW0014A_N 1522.36,3900 r270 top
U17 "OPA4197IPWR" PW0014A_N 1512.36,3050 r270 top
U18 "ADS8688IDBT" DBT0038A_N 2550.62,3469.95 r270 top
U19 "SN74LVC1G17DCKR" DCK0005A_N 2932.36,3190 r0 top
U20 "OPA4197IPWR" PW0014A_N 5622.05,2980 r90 top
U21 "OPA4197IPWR" PW0014A_N 5642.05,3850 r90 top
U22 "ADS8688IDBT" DBT0038A_N 4652.05,3370.31 r90 top
U23 "SN74LVC1G17DCKR" DCK0005A_N 4272.04,3730 r180 top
